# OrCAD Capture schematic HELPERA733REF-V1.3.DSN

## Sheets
1 00 Change log: title: HELPERA733_REF; rev: V1.3; company: szBaijie; note: Revision History
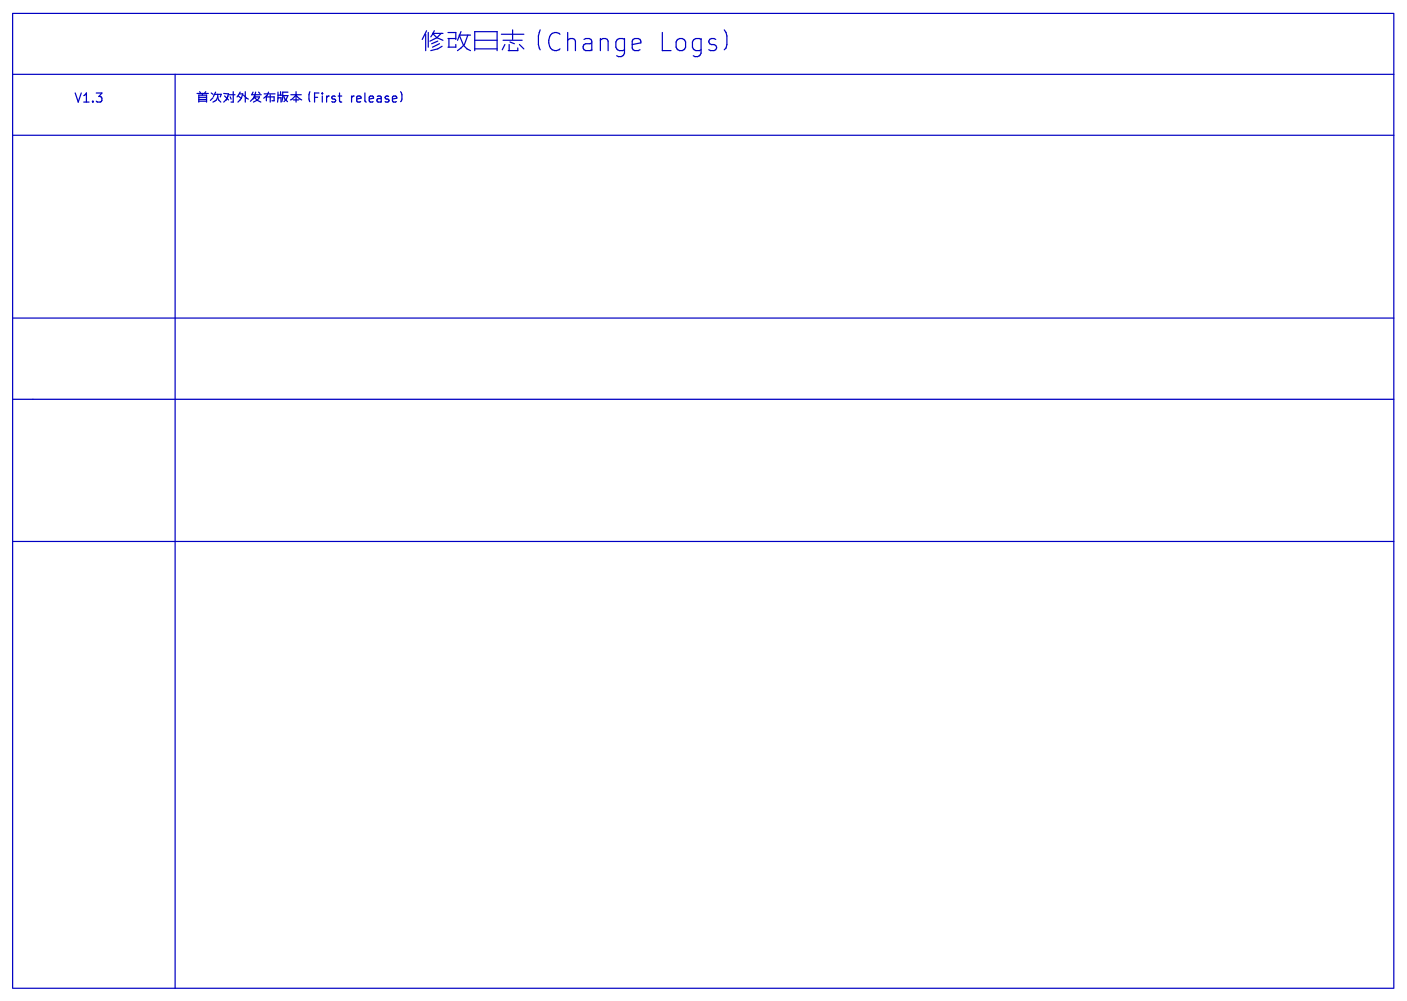
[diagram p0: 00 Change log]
2 01 CORE: size C; note: Core
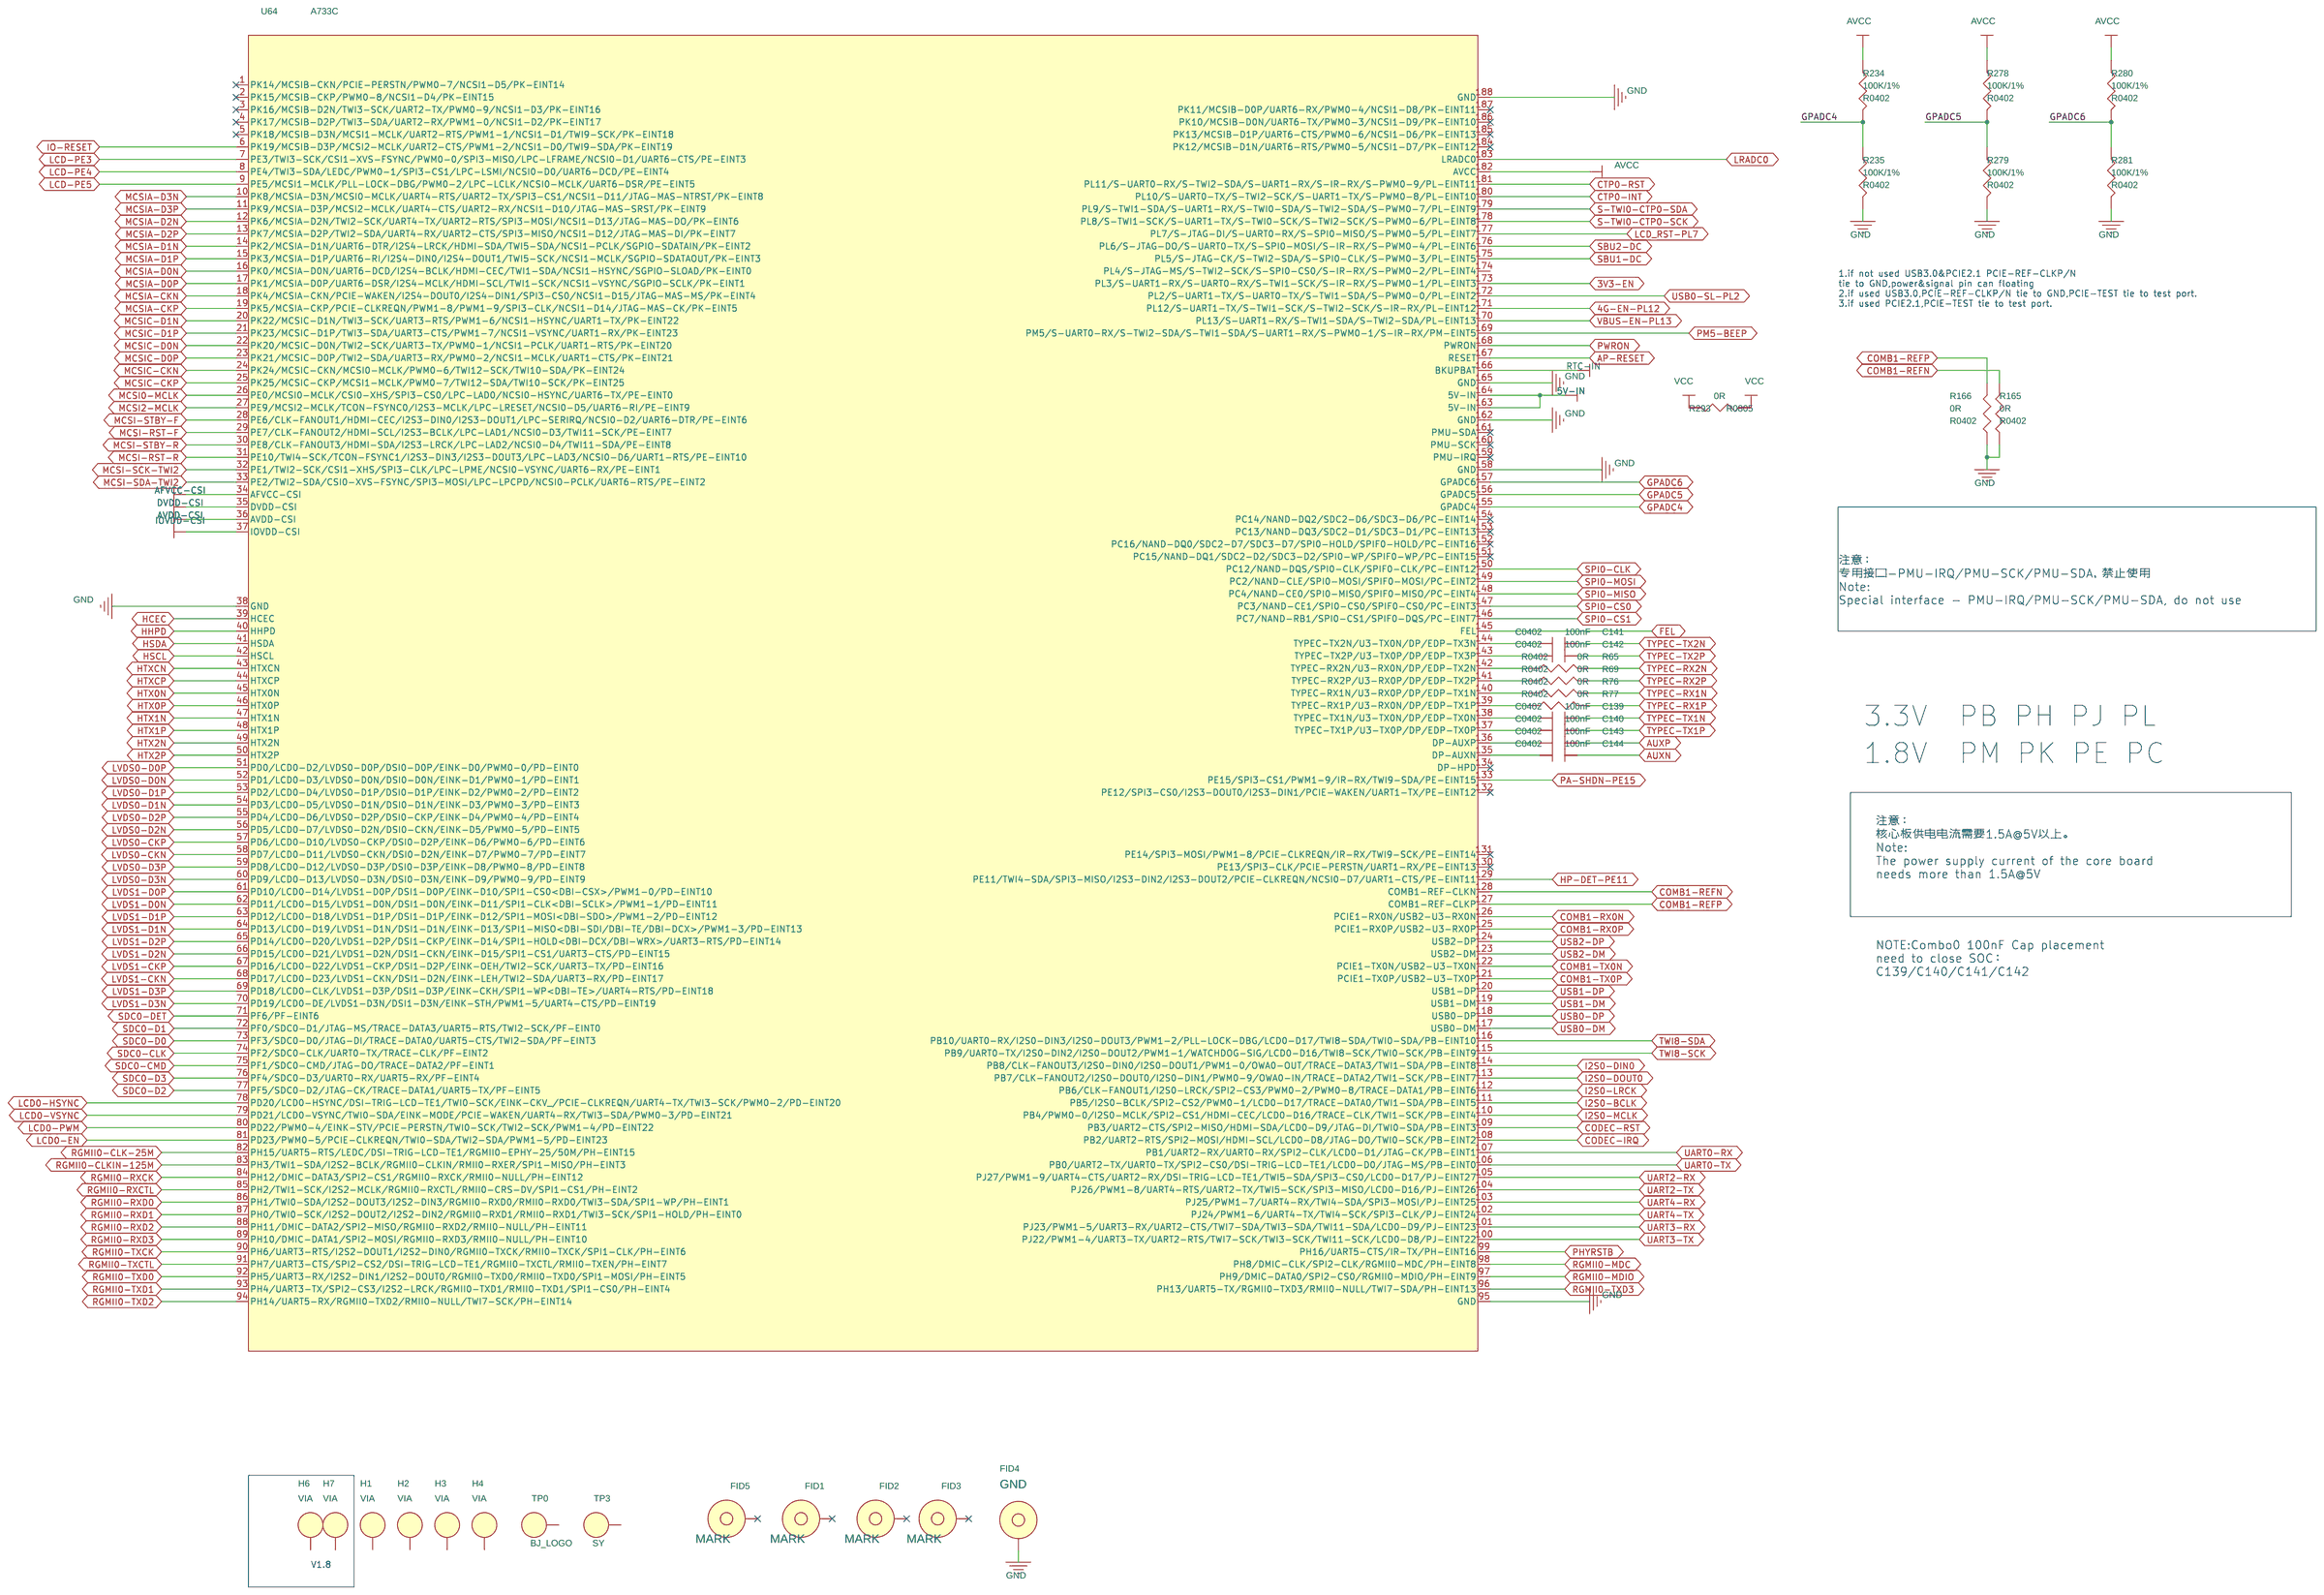
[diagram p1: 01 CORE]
3 02 Power: size B; note: Power
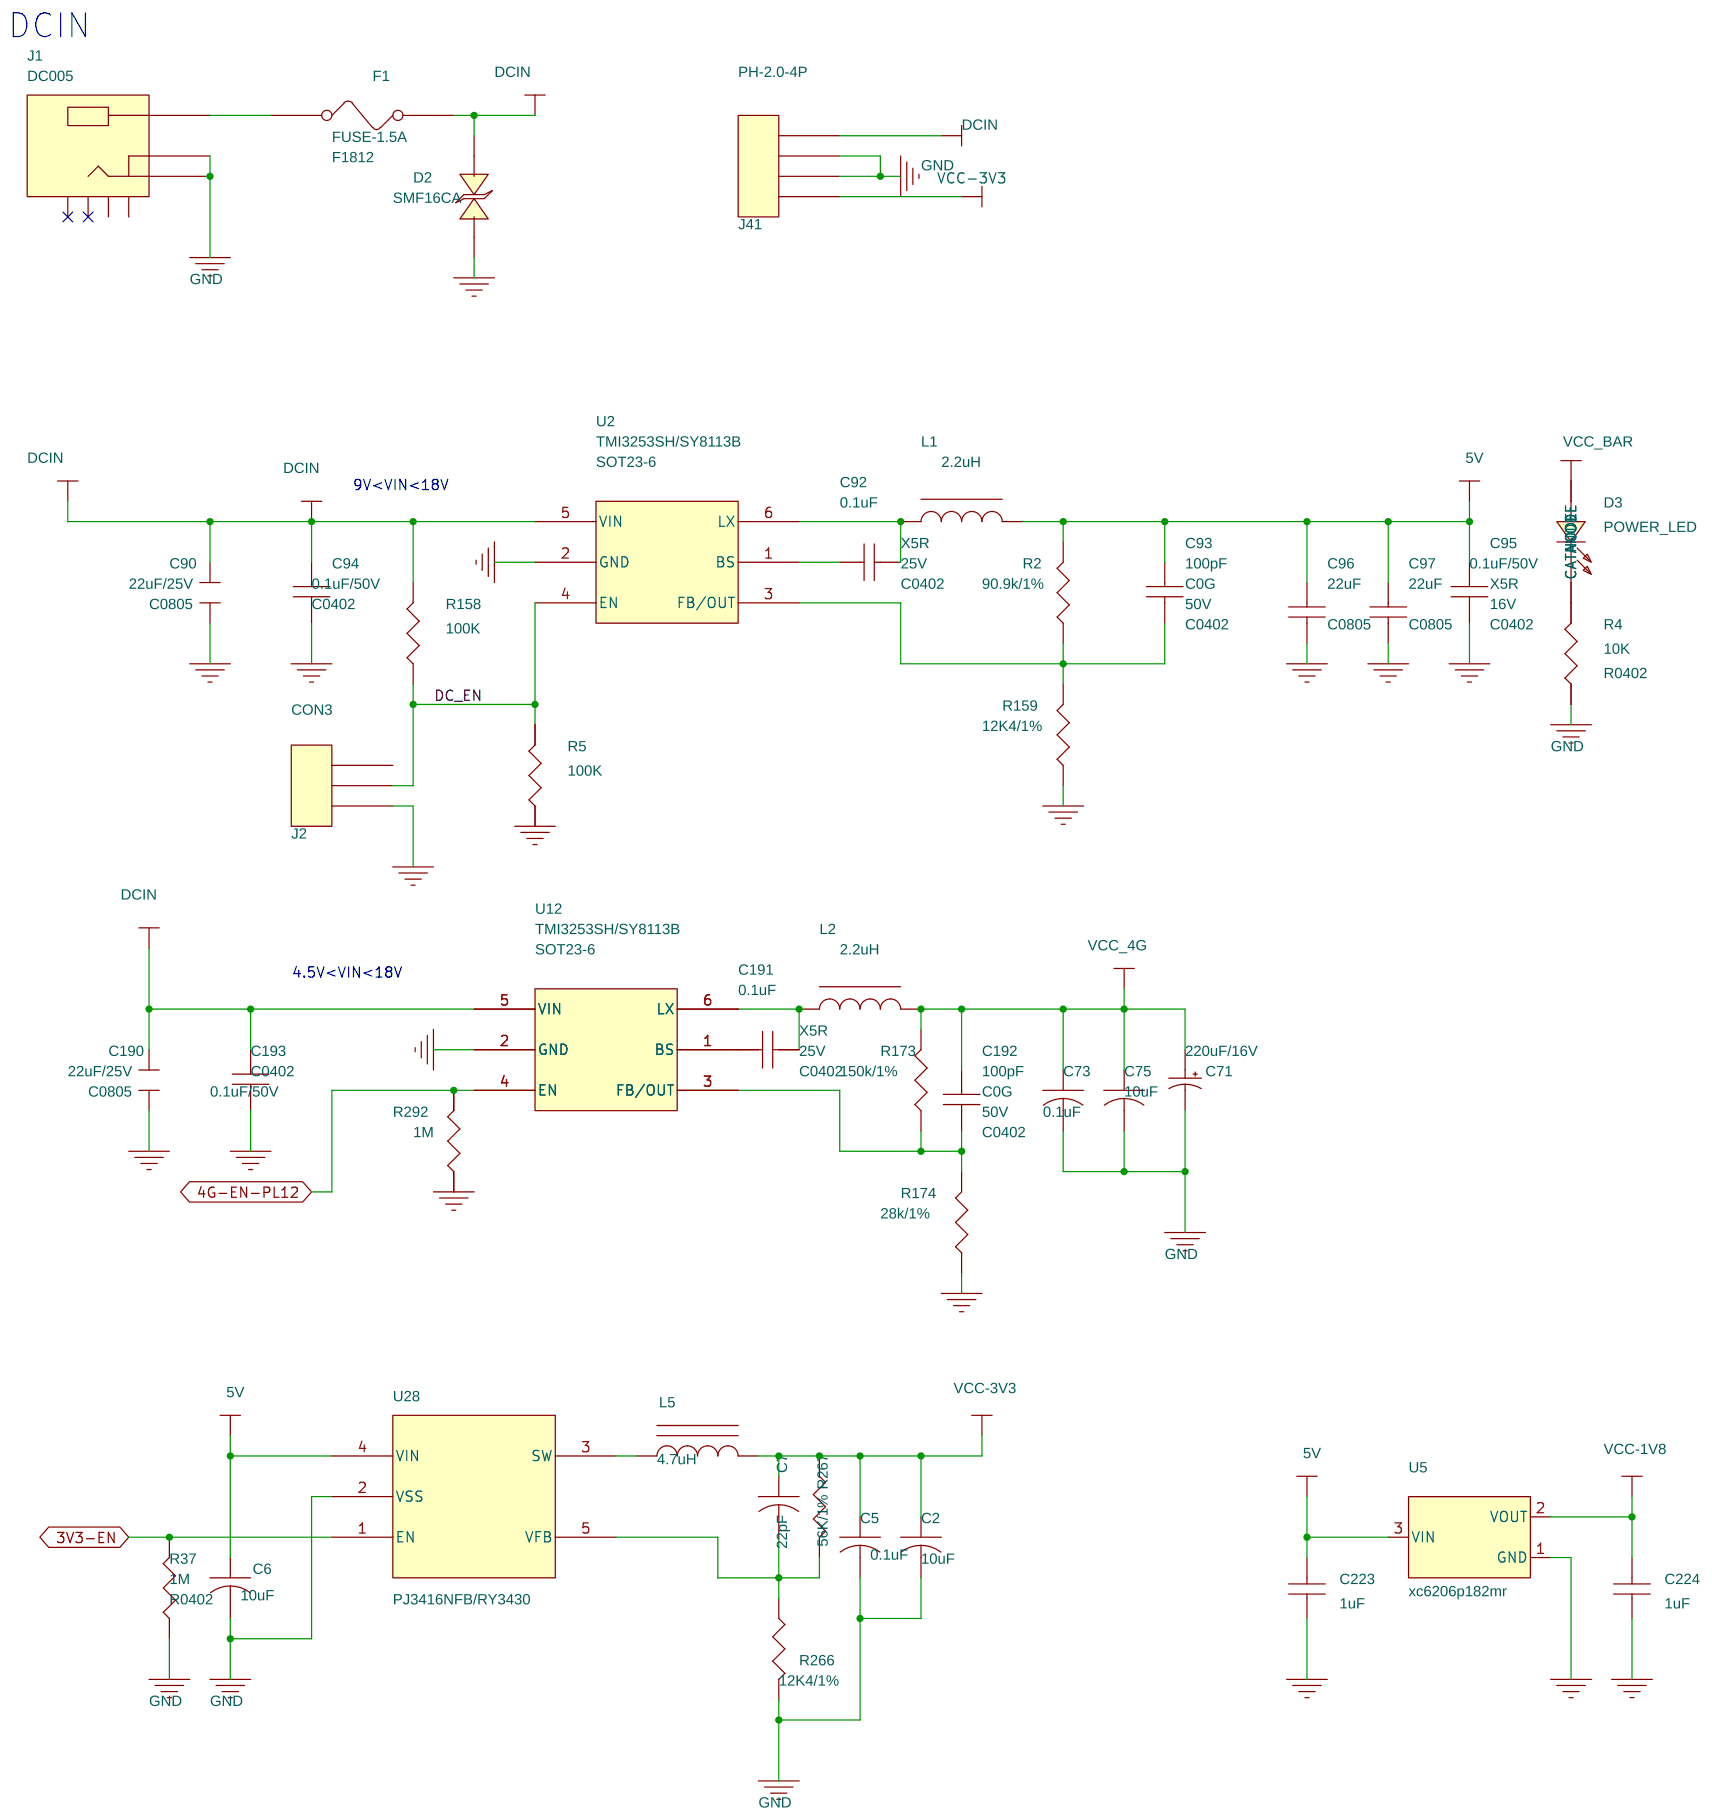
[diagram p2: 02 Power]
4 03 CAMERA: size Custom; note: Camera
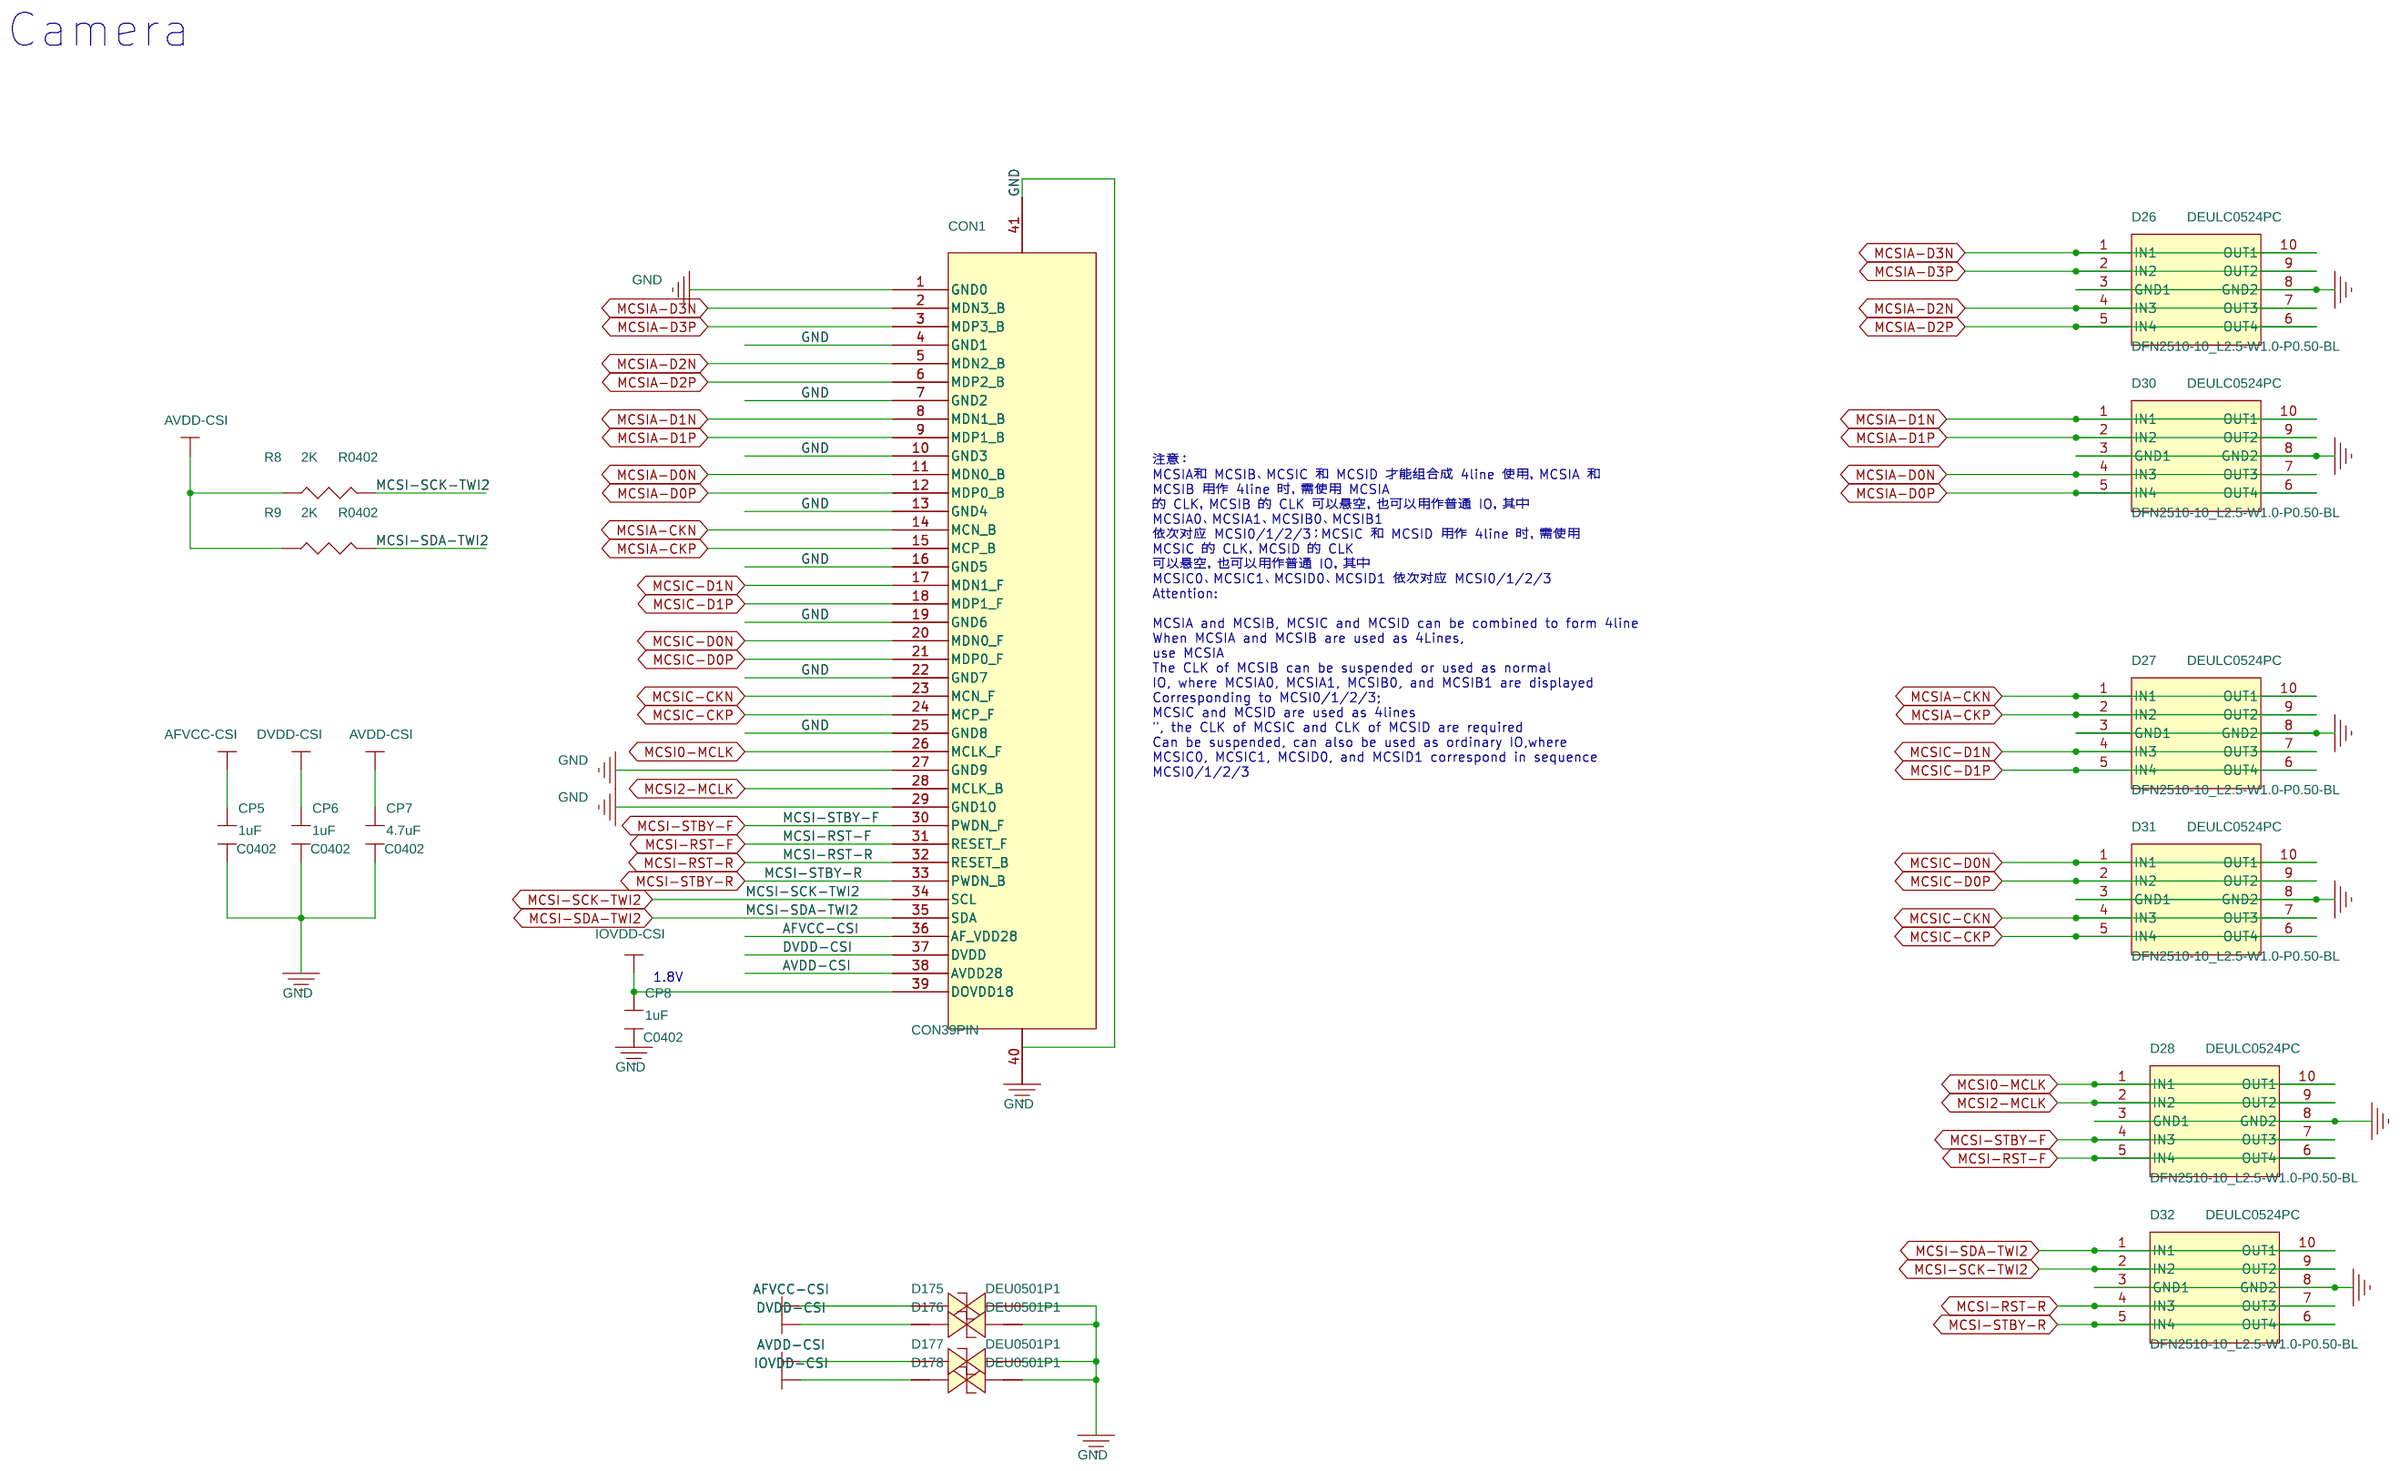
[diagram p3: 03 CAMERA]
5 04 LCD: size C; note: LCD
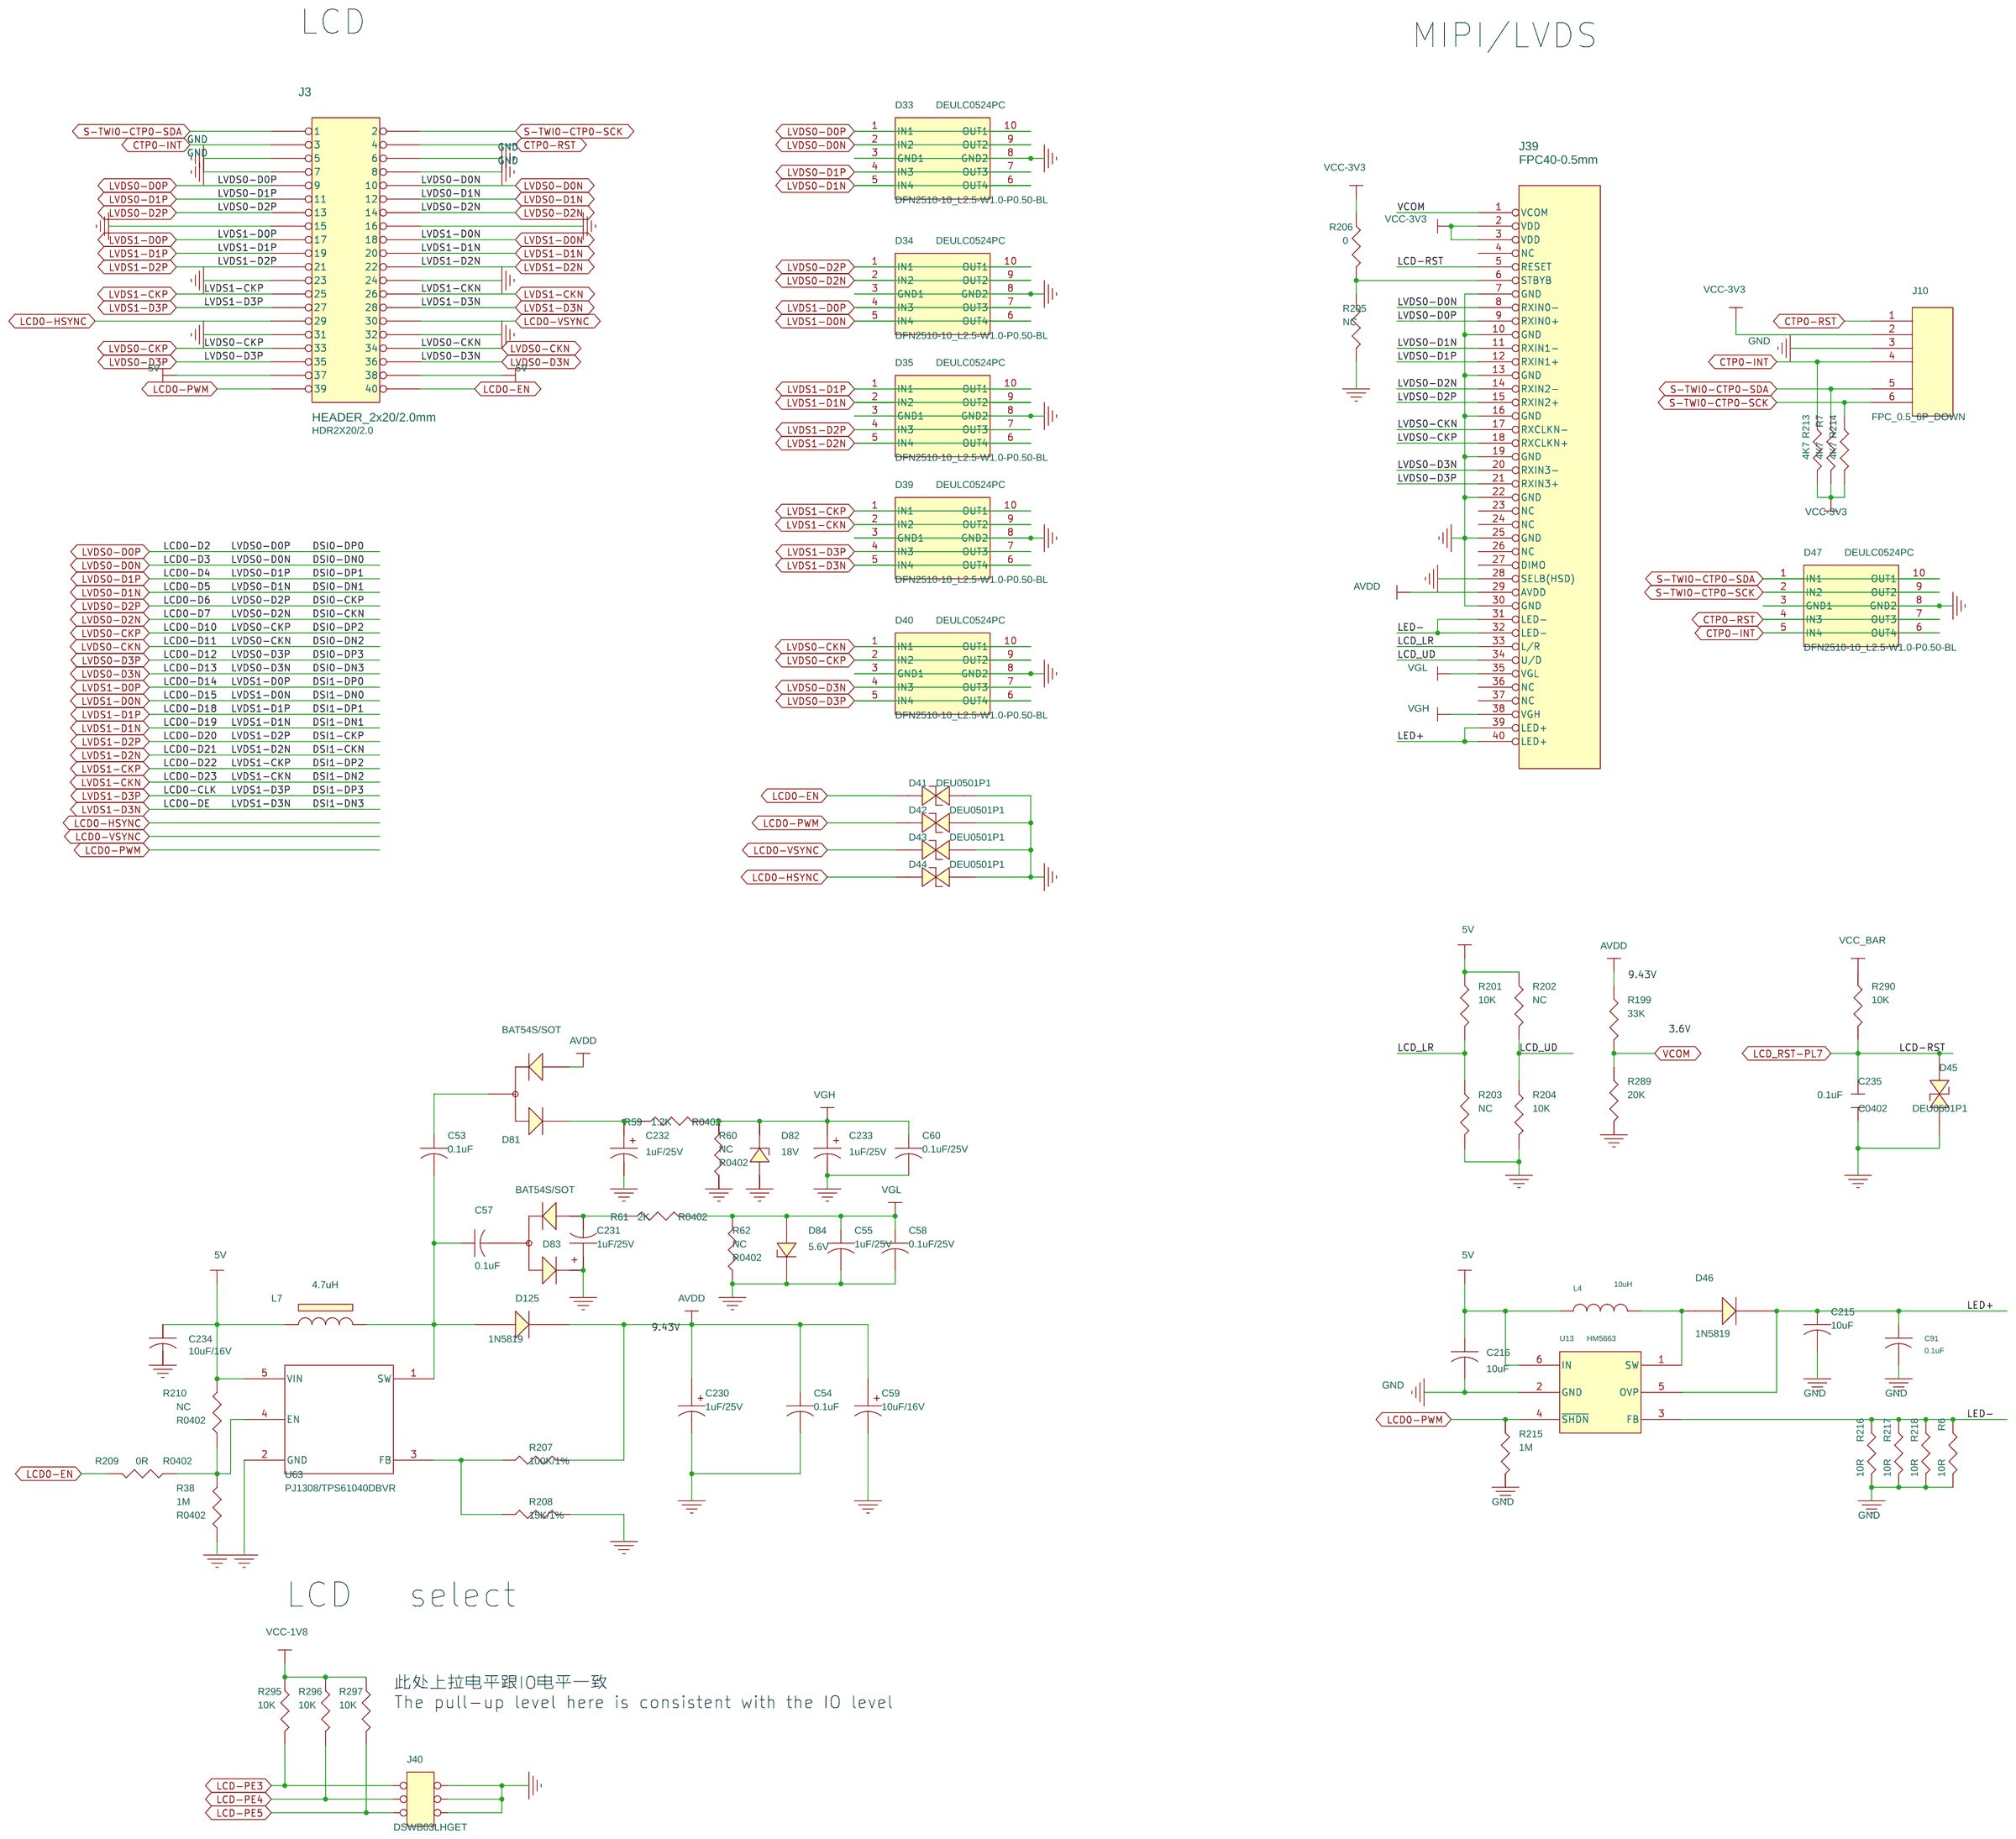
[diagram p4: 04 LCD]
6 07 4G: size A; note: 4G
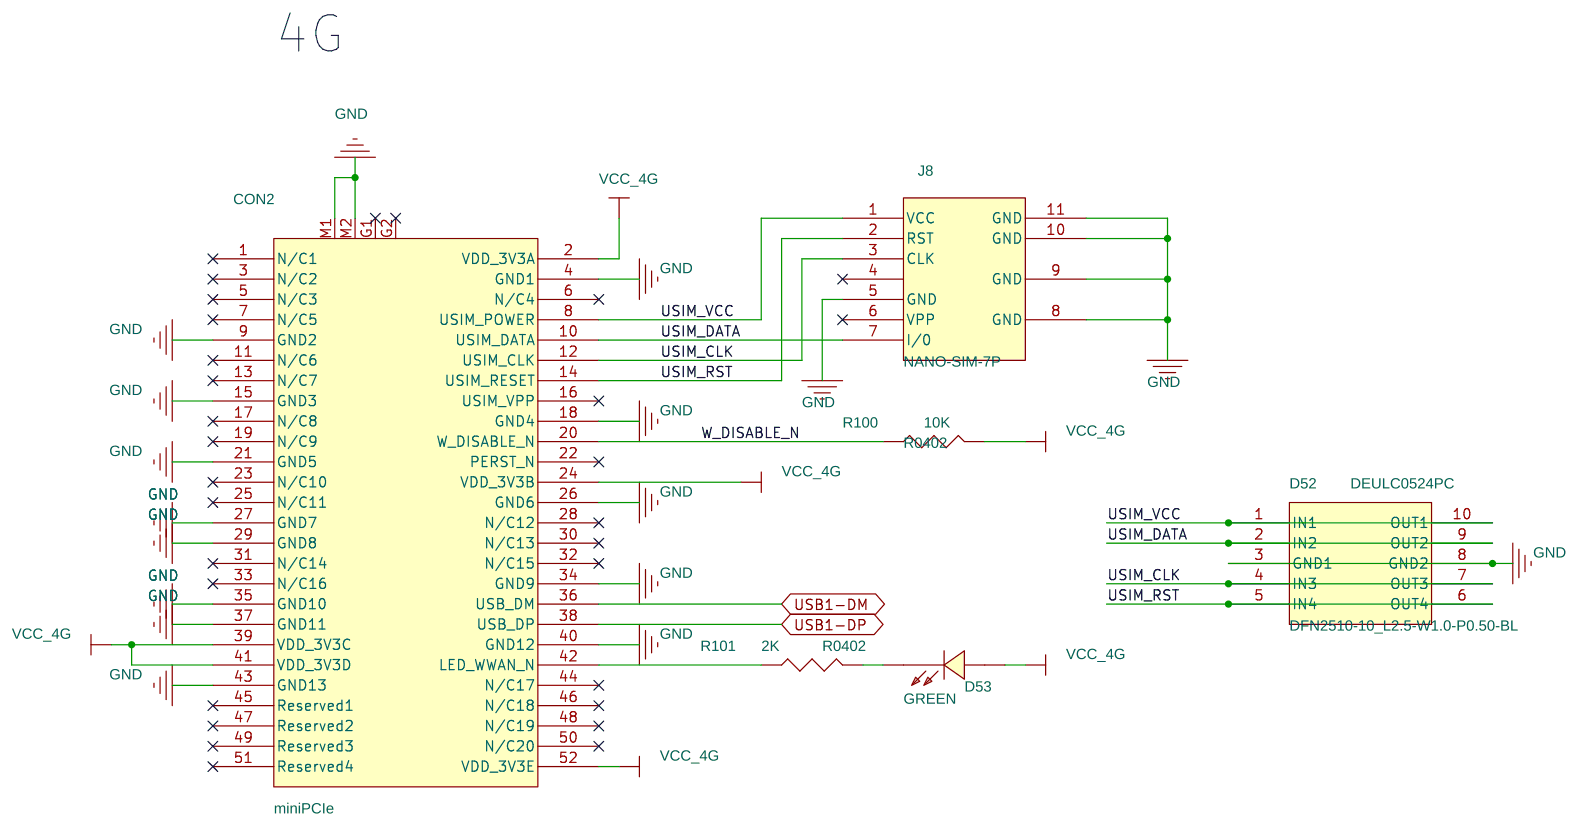
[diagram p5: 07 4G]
7 10 Ethernet: size B; note: Ethernet
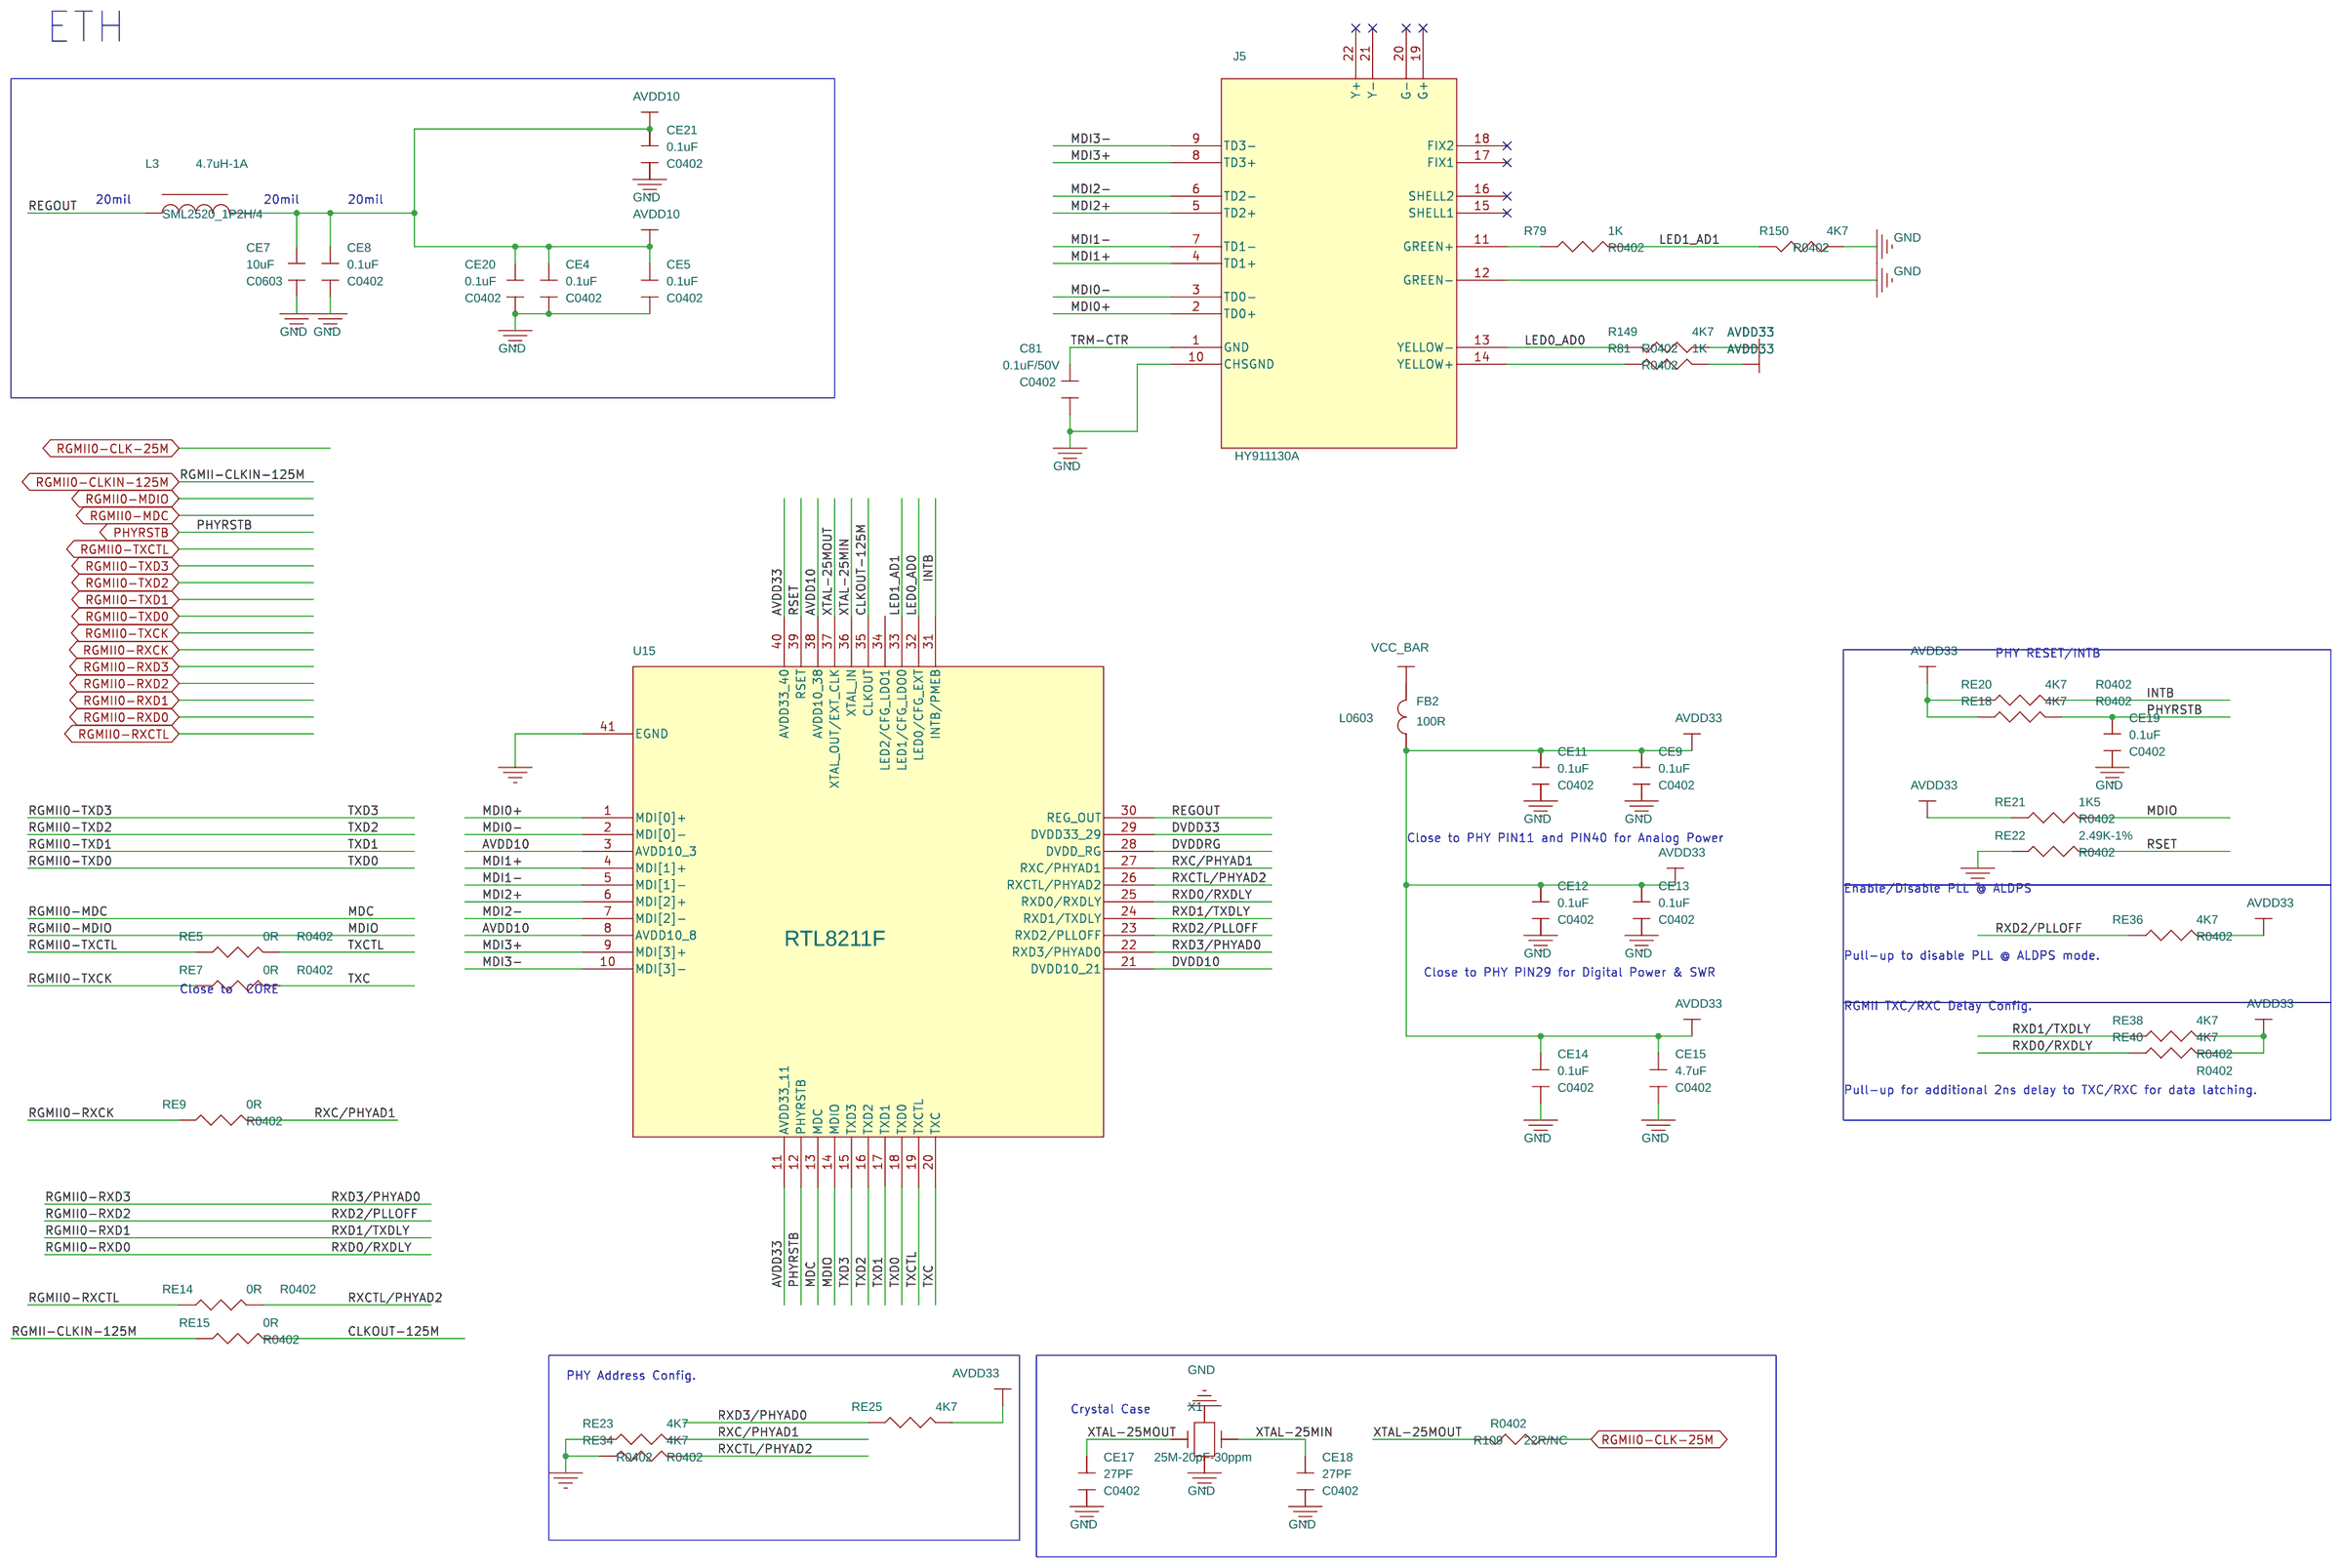
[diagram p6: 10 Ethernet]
8 12 HDMI: size A; note: HDMI
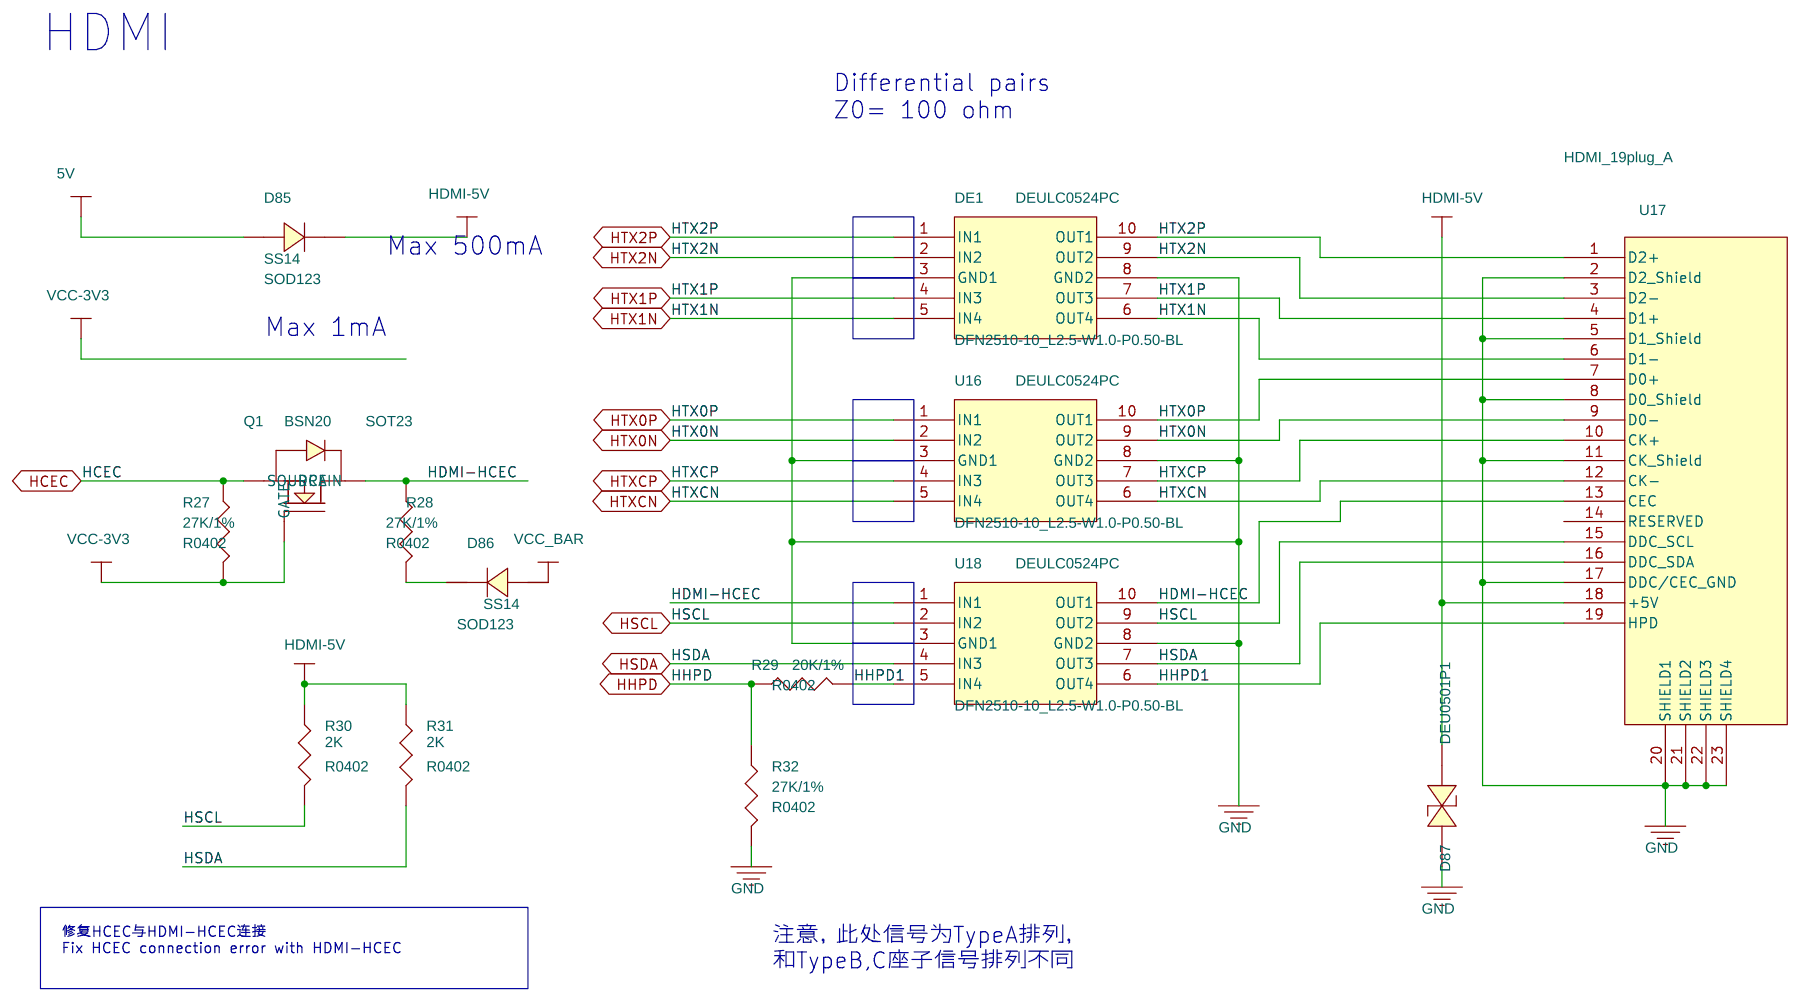
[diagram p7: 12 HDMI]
9 08  UART/485: size A; note: UART/485/CAN
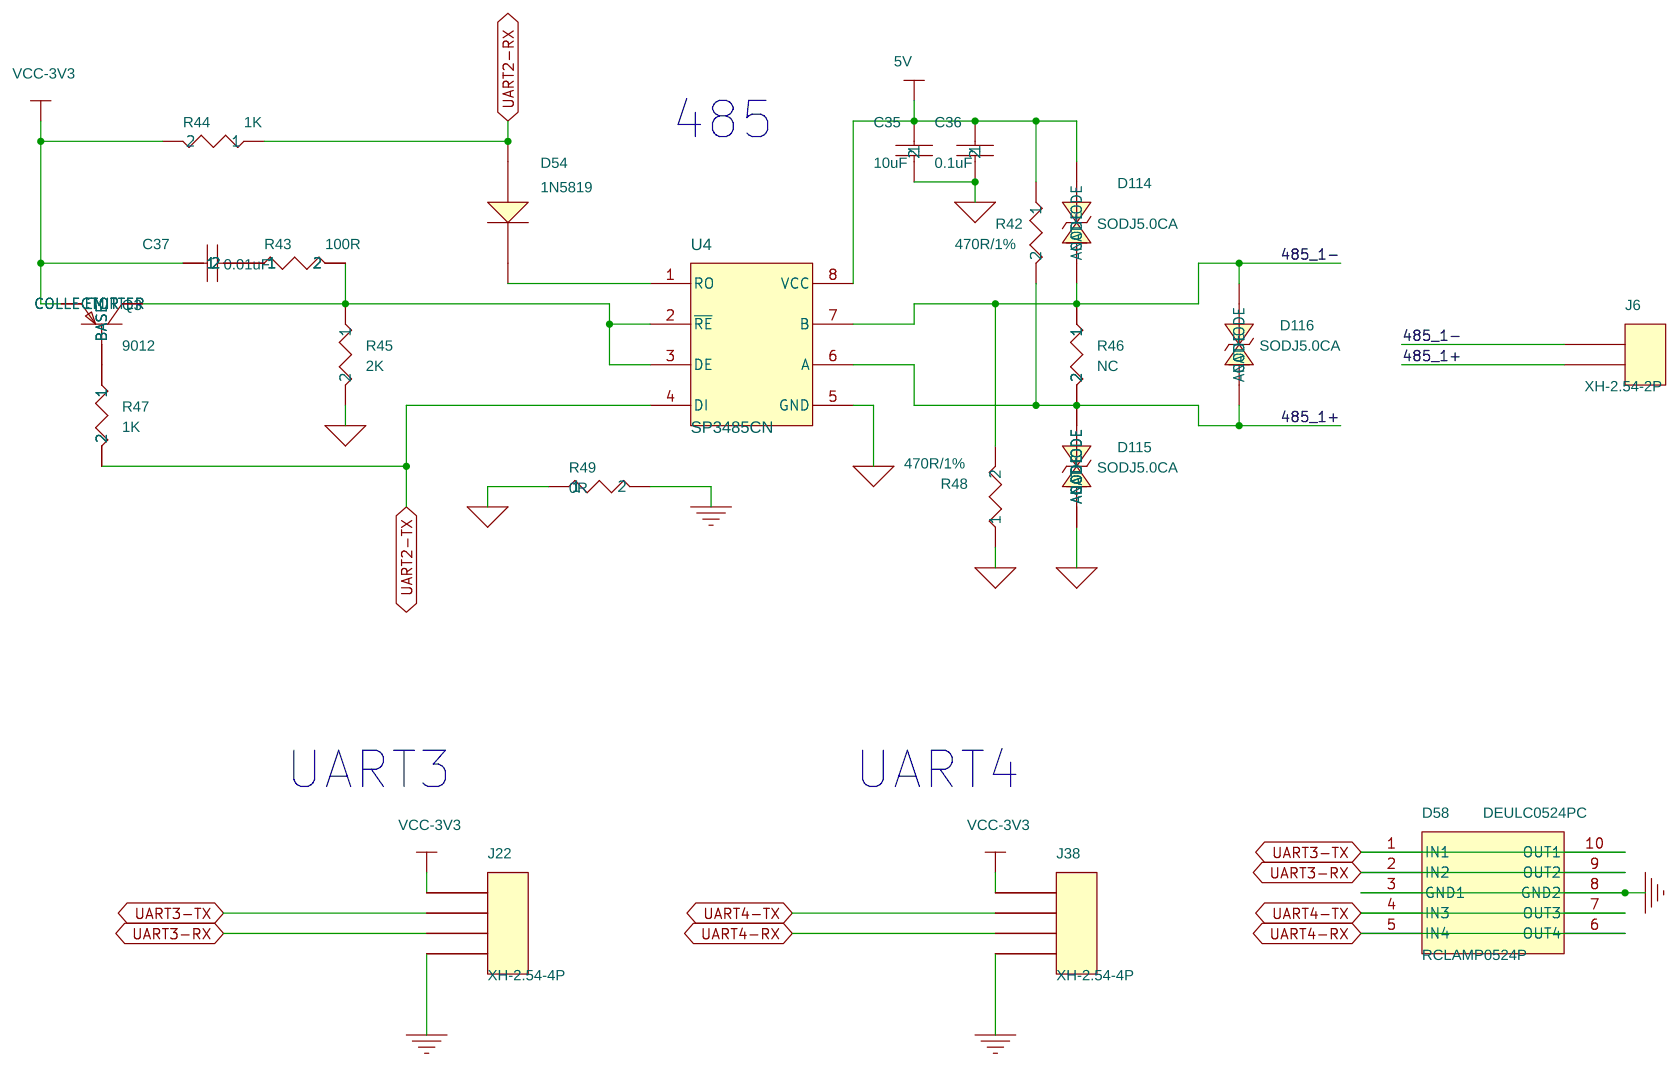
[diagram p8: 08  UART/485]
10 05 TF/KEY/RTC: size B; note: TF/KEY/RTC
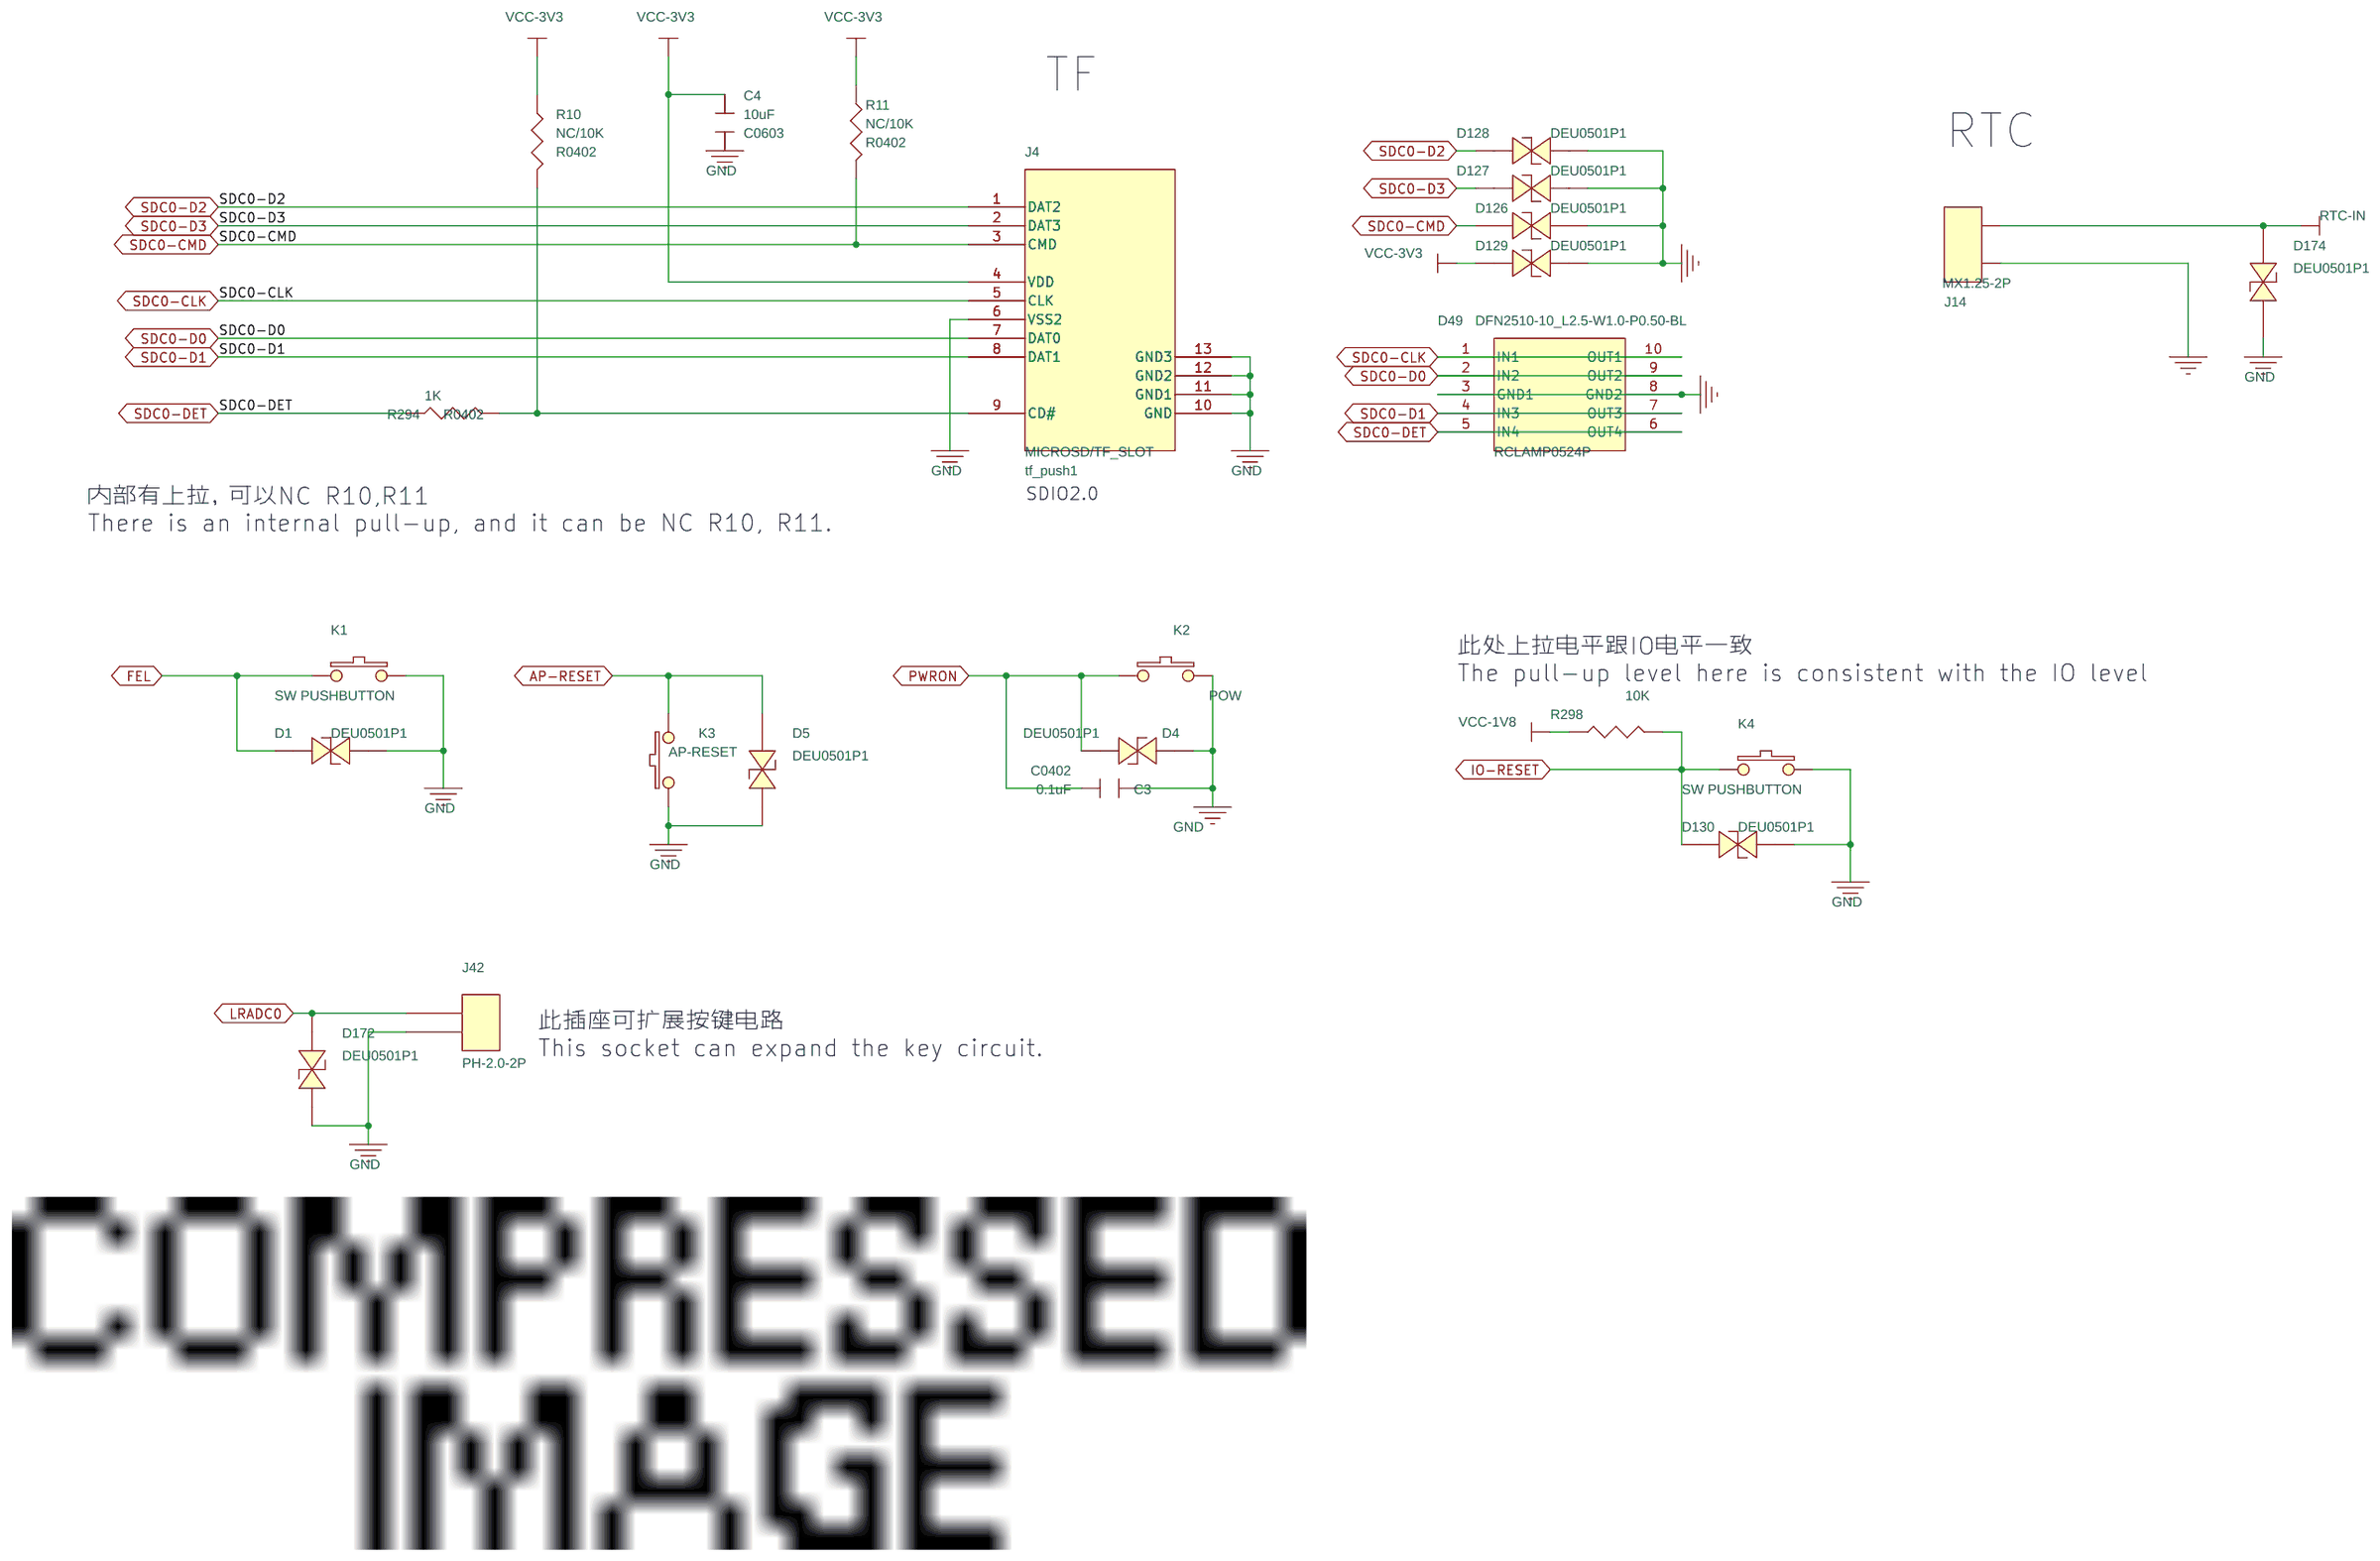
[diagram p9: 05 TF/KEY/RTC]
11 11 USB3.0/host: size C; note: USB3.0/host
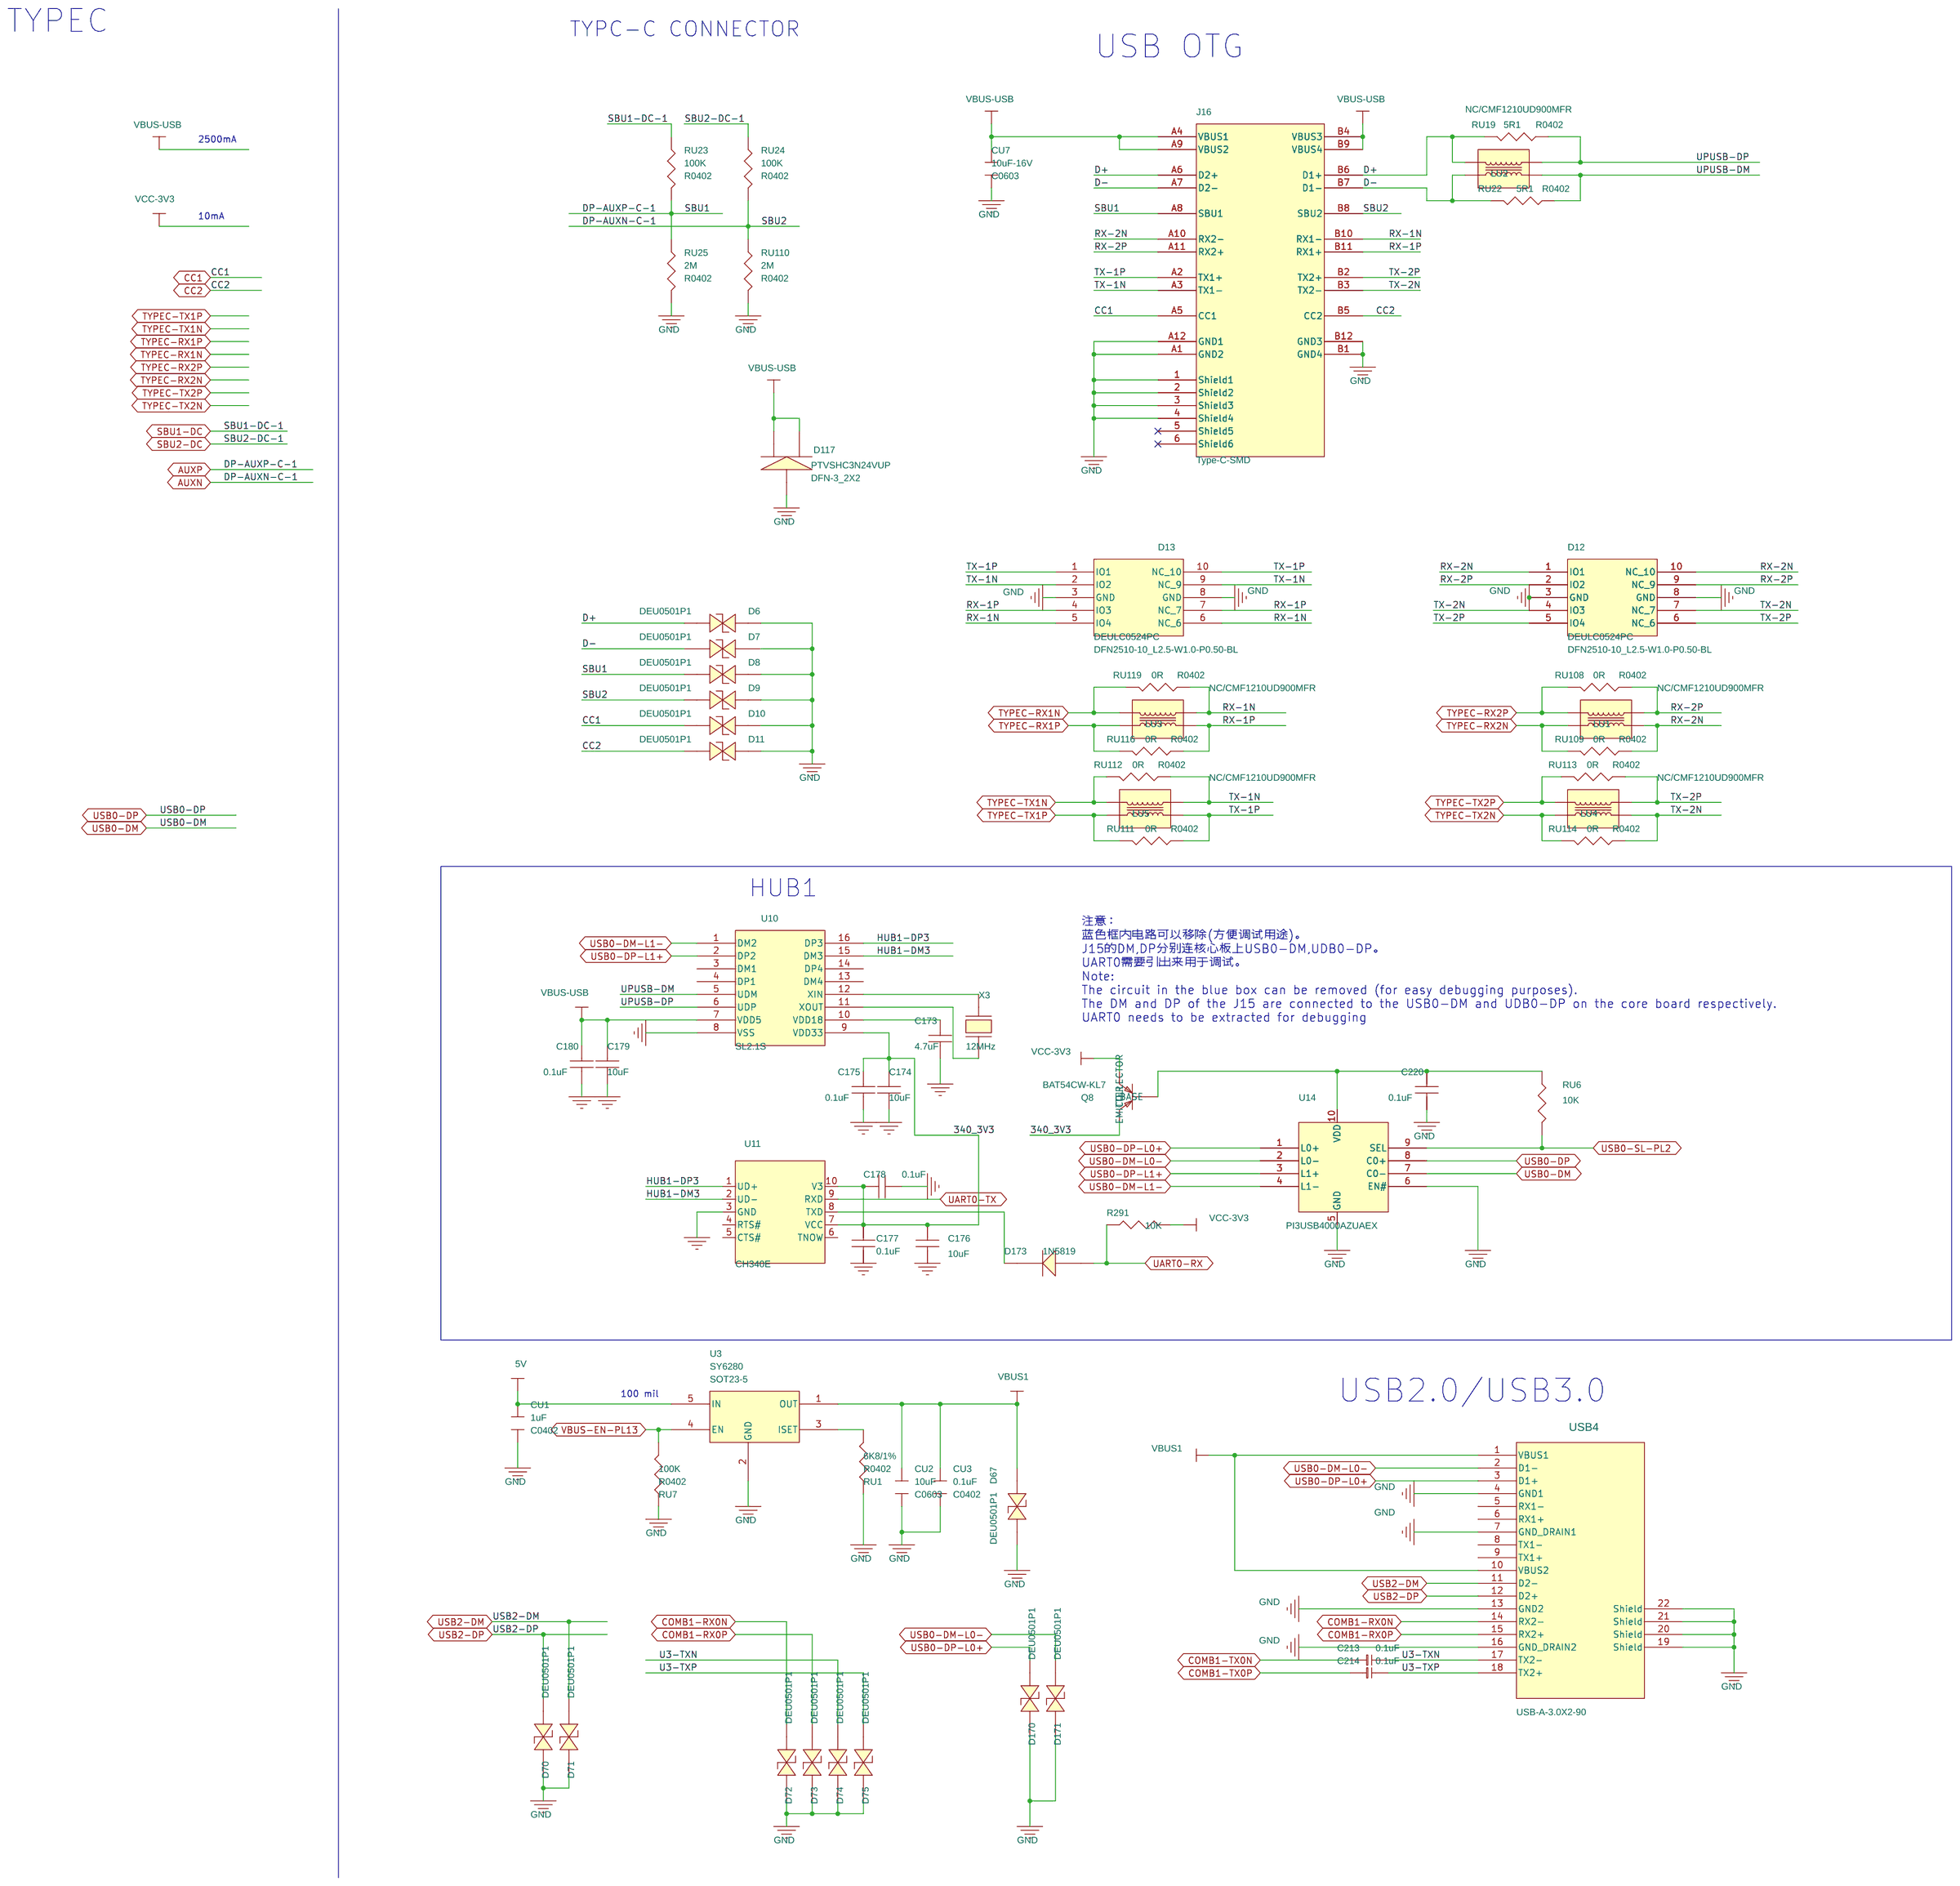
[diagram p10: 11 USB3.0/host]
12 09 IO/ADC/BEEP: size A; note: IO/ADC/BEEP
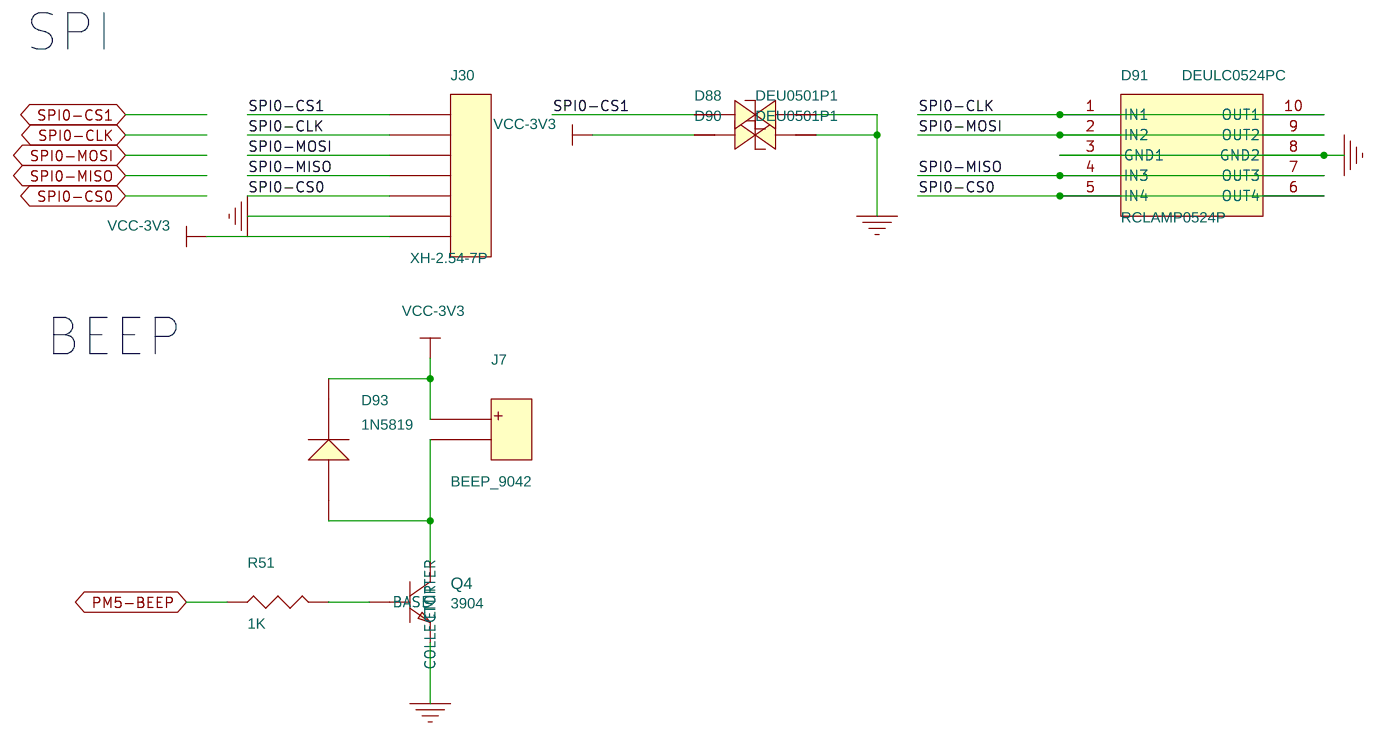
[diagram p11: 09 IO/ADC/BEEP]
13 06 AUDIO AC101/AC101B: size C; note: IO/ADC/BEEP
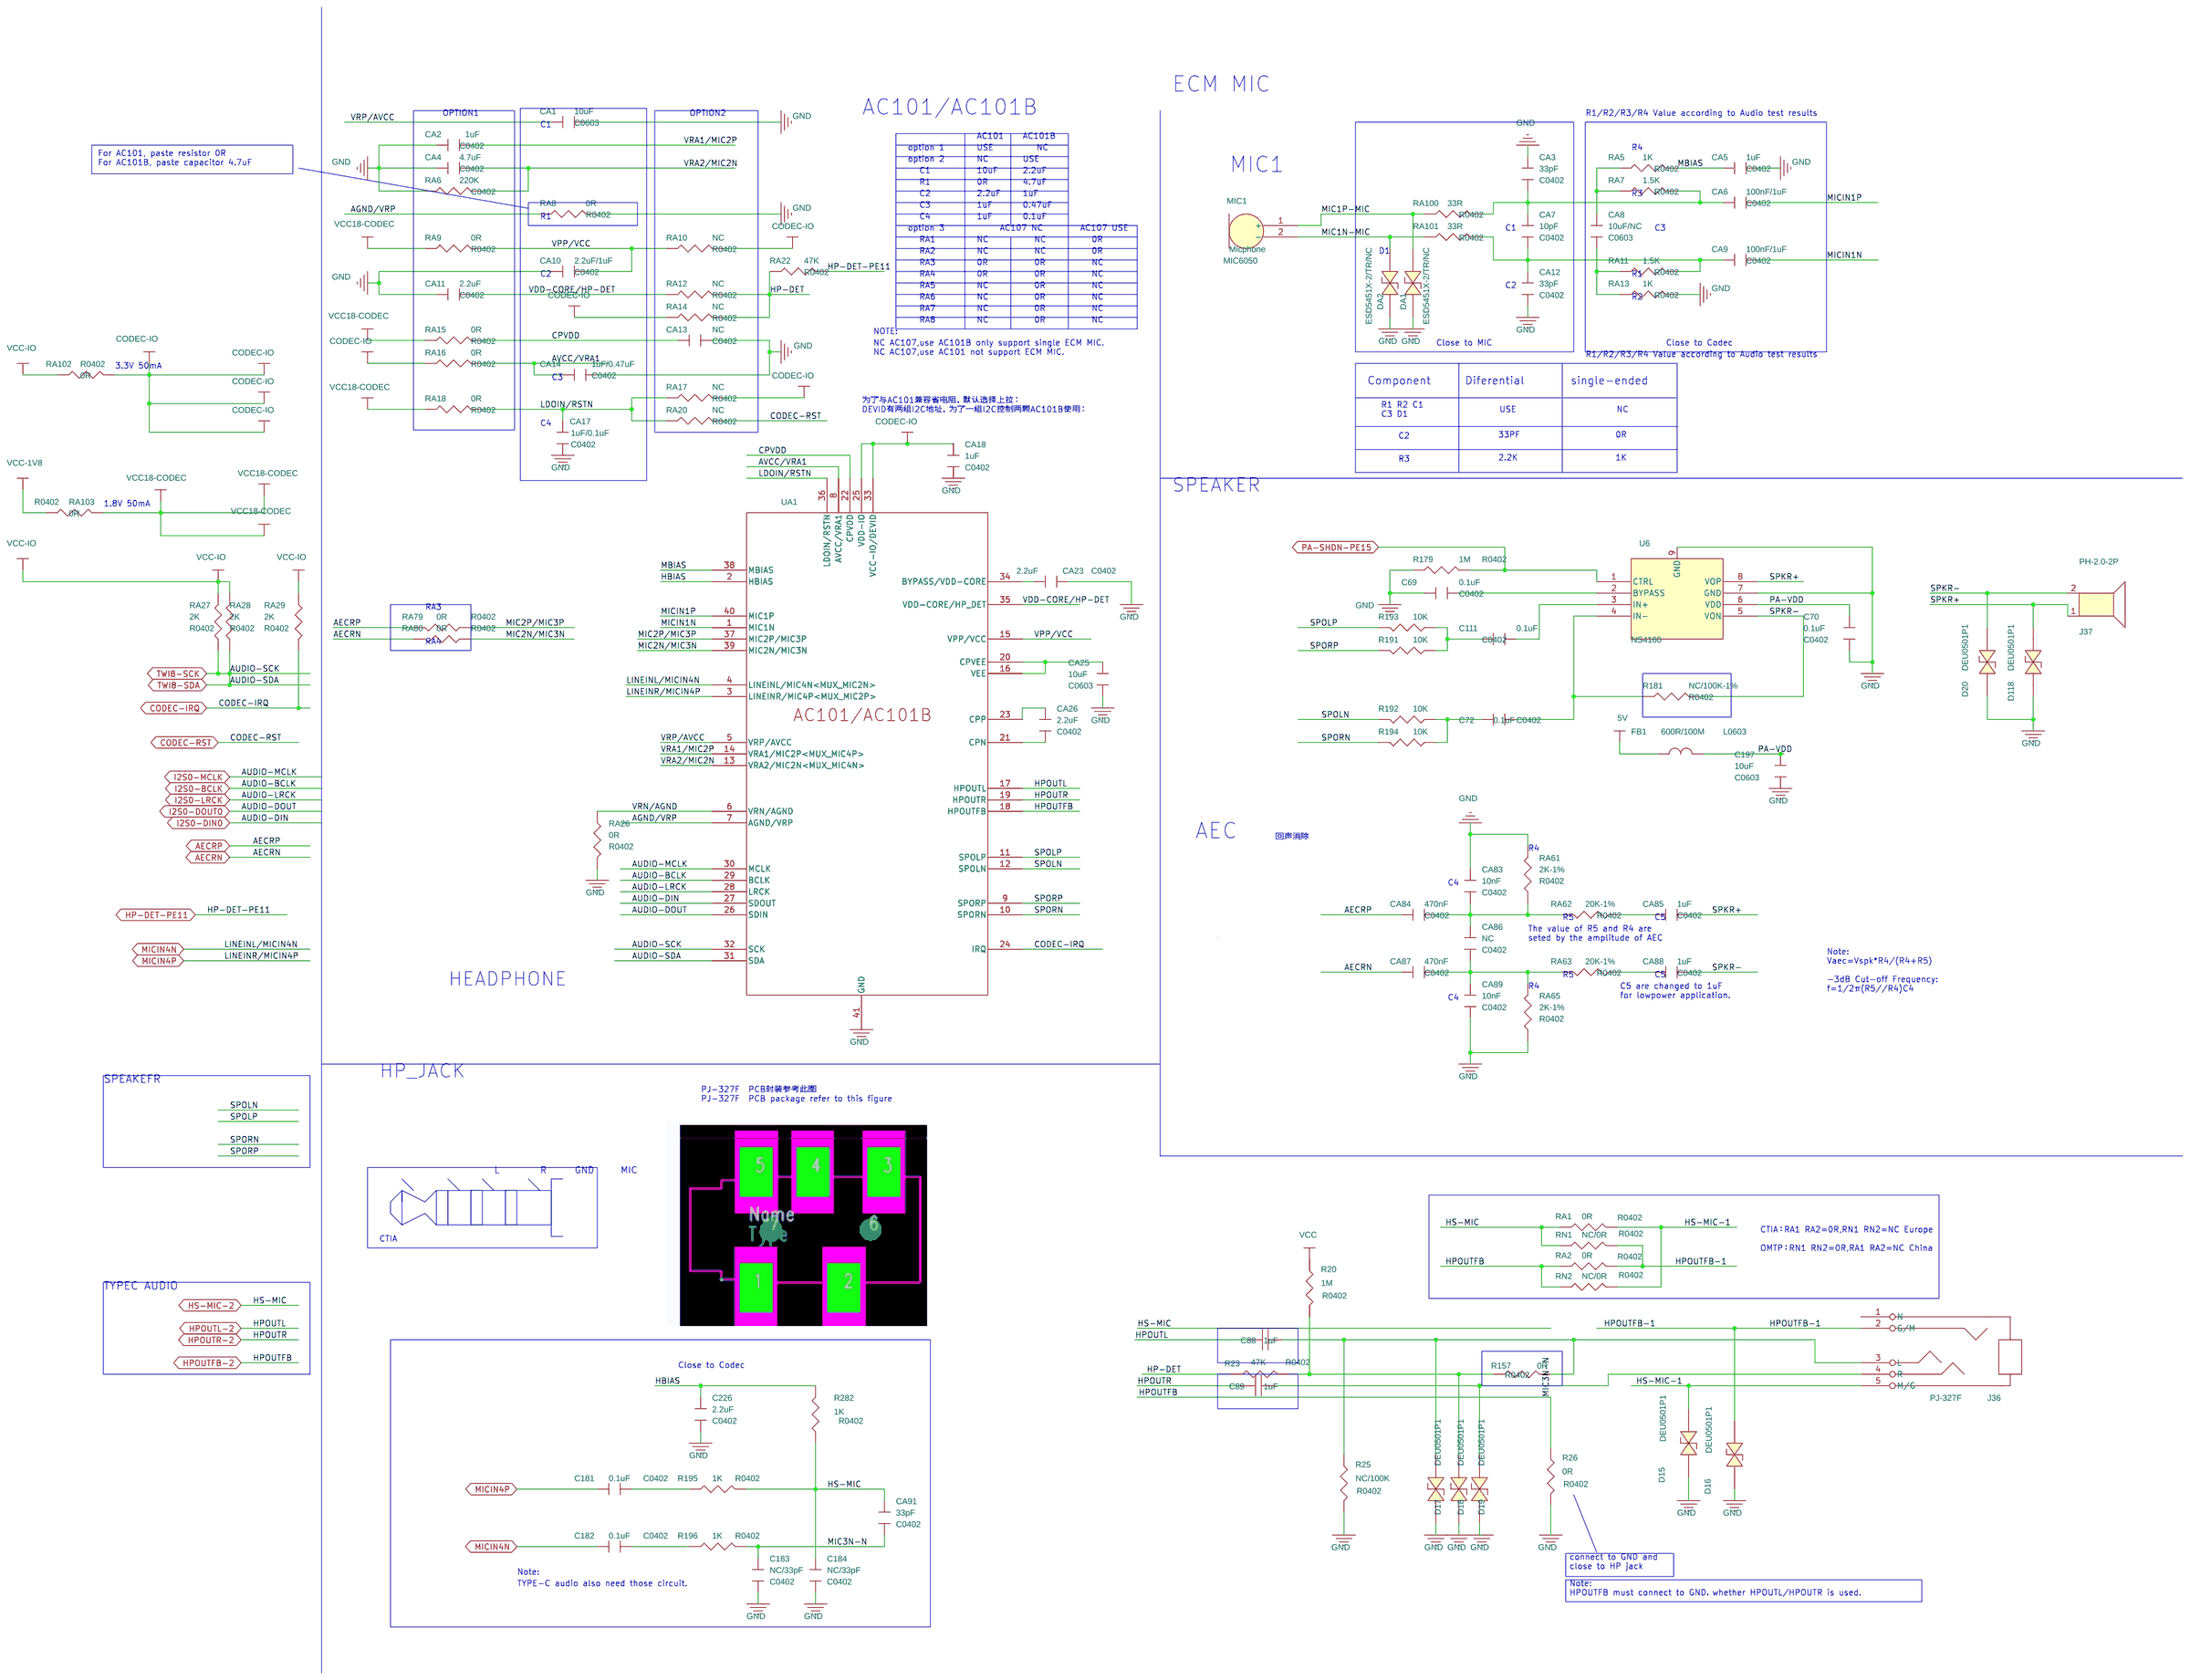
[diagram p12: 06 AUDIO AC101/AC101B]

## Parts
sheet 01 CORE
C139  100nF  [C0402]
C140  100nF  [C0402]
C141  100nF  [C0402]
C142  100nF  [C0402]
C143  100nF  [C0402]
C144  100nF  [C0402]
FID1  MARK  [MARK]
FID2  MARK  [MARK]
FID3  MARK  [MARK]
FID4  GND  [DV]
FID5  MARK  [MARK]
H1  VIA  [DV]
H2  VIA  [DV]
H3  VIA  [DV]
H4  VIA  [DV]
H6  VIA  [DV]
H7  VIA  [DV]
R65  0R  [R0402]
R69  0R  [R0402]
R76  0R  [R0402]
R77  0R  [R0402]
R165  0R  [R0402]
R166  0R  [R0402]
R234  100K/1%  [R0402]
R235  100K/1%  [R0402]
R278  100K/1%  [R0402]
R279  100K/1%  [R0402]
R280  100K/1%  [R0402]
R281  100K/1%  [R0402]
R293  0R  [R0805]
TP0  BJ_LOGO  [BJ_LOGO]
TP3  SY  [6X6]
U64  A733C  [HELPERA733D-1]
sheet 02 Power
C2  10uF  [C0603]
C5  0.1uF  [C0402]
C6  10uF  [C0603]
C7  22pF  [C0402]
C71  220uF/16V  [RB.1/.3]
C73  0.1uF  [C0402]
C75  10uF  [C0603]
C90  22uF/25V  [C0805]
C92  0.1uF  [C0402]
C93  100pF  [C0402]
C94  0.1uF/50V  [C0402]
C95  0.1uF/50V  [C0402]
C96  22uF  [C0805]
C97  22uF  [C0805]
C190  22uF/25V  [C0805]
C191  0.1uF  [C0402]
C192  100pF  [C0402]
C193  0.1uF/50V  [C0402]
C223  1uF  [C0402]
C224  1uF  [C0402]
D2  SMF16CA  [SOD123]
D3  POWER_LED  [D0603]
F1  FUSE-1.5A  [F1812]
J1  DC005  [DC470]
J2  CON3  [SS-12F44(1P2T)]
J41  PH-2.0-4P  [PH-2.0-4P]
L1  2.2uH  [4018]
L2  2.2uH  [4018]
L5  4.7uH  [4018]
R2  90.9k/1%  [R0402]
R4  10K  [R0402]
R5  100K  [R0402]
R37  1M  [R0402]
R158  100K  [R0402]
R159  12K4/1%  [R0402]
R173  150k/1%  [R0402]
R174  28k/1%  [R0402]
R266  12K4/1%  [R0402]
R267  56K/1%  [R0402]
R292  1M  [R0402]
U2  TMI3253SH/SY8113B  [SOT23-6]
U5  xc6206p182mr  [SOT23]
U12  TMI3253SH/SY8113B  [SOT23-6]
U28  PJ3416NFB/RY3430  [SOT23-5]
sheet 03 CAMERA
CON1  CON39PIN  [FH35C-39S-0.3SHW]
CP5  1uF  [C0402]
CP6  1uF  [C0402]
CP7  4.7uF  [C0402]
CP8  1uF  [C0402]
D26  DEULC0524PC  [DFN2510-10_L2.5-W1.0-P0.50-BL]
D27  DEULC0524PC  [DFN2510-10_L2.5-W1.0-P0.50-BL]
D28  DEULC0524PC  [DFN2510-10_L2.5-W1.0-P0.50-BL]
D30  DEULC0524PC  [DFN2510-10_L2.5-W1.0-P0.50-BL]
D31  DEULC0524PC  [DFN2510-10_L2.5-W1.0-P0.50-BL]
D32  DEULC0524PC  [DFN2510-10_L2.5-W1.0-P0.50-BL]
D175  DEU0501P1  [ESD0402]
D176  DEU0501P1  [ESD0402]
D177  DEU0501P1  [ESD0402]
D178  DEU0501P1  [ESD0402]
R8  2K  [R0402]
R9  2K  [R0402]
sheet 04 LCD
C53  0.1uF  [C0402]
C54  0.1uF  [C0402]
C55  1uF/25V  [C0805]
C57  0.1uF  [C0402]
C58  0.1uF/25V  [C0402]
C59  10uF/16V  [C0805]
C60  0.1uF/25V  [C0402]
C91  0.1uF  [C0402]
C215  10uF  [C0603]
C216  10uF  [C0603]
C230  1uF/25V  [C0805]
C231  1uF/25V  [C0805]
C232  1uF/25V  [C0805]
C233  1uF/25V  [C0805]
C234  10uF/16V  [C0805]
C235  0.1uF  [C0402]
D33  DEULC0524PC  [DFN2510-10_L2.5-W1.0-P0.50-BL]
D34  DEULC0524PC  [DFN2510-10_L2.5-W1.0-P0.50-BL]
D35  DEULC0524PC  [DFN2510-10_L2.5-W1.0-P0.50-BL]
D39  DEULC0524PC  [DFN2510-10_L2.5-W1.0-P0.50-BL]
D40  DEULC0524PC  [DFN2510-10_L2.5-W1.0-P0.50-BL]
D41  DEU0501P1  [ESD0402]
D42  DEU0501P1  [ESD0402]
D43  DEU0501P1  [ESD0402]
D44  DEU0501P1  [ESD0402]
D45  DEU0501P1  [ESD0402]
D46  1N5819  [SOD323]
D47  DEULC0524PC  [DFN2510-10_L2.5-W1.0-P0.50-BL]
D81  BAT54S/SOT  [SOT23]
D82  18V  [D0805]
D83  BAT54S/SOT  [SOT23]
D84  5.6V  [D0805]
D125  1N5819  [D0805]
J3  HEADER_2x20/2.0mm  [HDR2X20/2.0]
J10  FPC_0.5_6P_DOWN  [FPC_0.5_6P_DOWN]
J39  FPC40-0.5mm  [FPC40-0.5MM-UP]
J40  DSWB03LHGET  [SW-TH-DSWB03LHGET]
L4  10uH  [4018]
L7  4.7uH  [4018]
R6  10R  [R0402]
R7  4K7  [R0402]
R38  1M  [R0402]
R59  1.2K  [R0402]
R60  NC  [R0402]
R61  2K  [R0402]
R62  NC  [R0402]
R199  33K  [R0402]
R201  10K  [R0402]
R202  NC  [R0402]
R203  NC  [R0402]
R204  10K  [R0402]
R205  NC  [R0402]
R206  0  [R0402]
R207  100K/1%  [R0402]
R208  15K/1%  [R0402]
R209  0R  [R0402]
R210  NC  [R0402]
R213  4K7  [R0402]
R214  4K7  [R0402]
R215  1M  [R0402]
R216  10R  [R0402]
R217  10R  [R0402]
R218  10R  [R0402]
R289  20K  [R0402]
R290  10K  [R0402]
R295  10K  [R0402]
R296  10K  [R0402]
R297  10K  [R0402]
U13  HM5663  [SOT23-6]
U63  PJ1308/TPS61040DBVR  [SOT23-5]
sheet 05 TF/KEY/RTC
C3  0.1uF  [C0402]
C4  10uF  [C0603]
D1  DEU0501P1  [ESD0402]
D4  DEU0501P1  [ESD0402]
D5  DEU0501P1  [ESD0402]
D49  DFN2510-10_L2.5-W1.0-P0.50-BL  [RCLAMP0524P]
D126  DEU0501P1  [ESD0402]
D127  DEU0501P1  [ESD0402]
D128  DEU0501P1  [ESD0402]
D129  DEU0501P1  [ESD0402]
D130  DEU0501P1  [ESD0402]
D172  DEU0501P1  [ESD0402]
D174  DEU0501P1  [ESD0402]
J4  MICROSD/TF_SLOT  [tf_push1]
J14  MX1.25-2P  [MX1.25-2P]
J42  PH-2.0-2P  [PH-2.0-2P]
K1  SW PUSHBUTTON  [KEY_3X4]
K2  POW  [KEY_3X4]
K3  AP-RESET  [KEY_3X4]
K4  SW PUSHBUTTON  [KEY_3X4]
R10  NC/10K  [R0402]
R11  NC/10K  [R0402]
R294  1K  [R0402]
R298  10K  [R0402]
sheet 06 AUDIO AC101/AC101B
C69  0.1uF  [C0402]
C70  0.1uF  [C0402]
C72  0.1uF  [C0402]
C88  1uF  [C0402]
C89  1uF  [C0402]
C111  0.1uF  [C0402]
C181  0.1uF  [C0402]
C182  0.1uF  [C0402]
C183  NC/33pF  [C0402]
C184  NC/33pF  [C0402]
C197  10uF  [C0603]
C226  2.2uF  [C0402]
CA1  10uF  [C0603]
CA2  1uF  [C0402]
CA3  33pF  [C0402]
CA4  4.7uF  [C0402]
CA5  1uF  [C0402]
CA6  100nF/1uF  [C0402]
CA7  10pF  [C0402]
CA8  10uF/NC  [C0603]
CA9  100nF/1uF  [C0402]
CA10  2.2uF/1uF  [C0402]
CA11  2.2uF  [C0402]
CA12  33pF  [C0402]
CA13  NC  [C0402]
CA14  1uF/0.47uF  [C0402]
CA17  1uF/0.1uF  [C0402]
CA18  1uF  [C0402]
CA23  2.2uF  [C0402]
CA25  10uF  [C0603]
CA26  2.2uF  [C0402]
CA83  10nF  [C0402]
CA84  470nF  [C0402]
CA85  1uF  [C0402]
CA86  NC  [C0402]
CA87  470nF  [C0402]
CA88  1uF  [C0402]
CA89  10nF  [C0402]
CA91  33pF  [C0402]
D15  DEU0501P1  [ESD0402]
D16  DEU0501P1  [ESD0402]
D17  DEU0501P1  [ESD0402]
D18  DEU0501P1  [ESD0402]
D19  DEU0501P1  [ESD0402]
D20  DEU0501P1  [ESD0402]
D118  DEU0501P1  [ESD0402]
DA1  ESD5451X-2/TR/NC  [ESD0402]
DA2  ESD5451X-2/TR/NC  [ESD0402]
FB1  600R/100M  [L0603]
J36  PJ-327F  [PJ327F]
J37  PH-2.0-2P  [PH-2.0-2P]
MIC1  Micphone  [MIC6050]
R20  1M  [R0402]
R23  47K  [R0402]
R25  NC/100K  [R0402]
R26  0R  [R0402]
R157  0R  [R0402]
R179  1M  [R0402]
R181  NC/100K-1%  [R0402]
R191  10K  [R0402]
R192  10K  [R0402]
R193  10K  [R0402]
R194  10K  [R0402]
R195  1K  [R0402]
R196  1K  [R0402]
R282  1K  [R0402]
RA1  0R  [R0402]
RA2  0R  [R0402]
RA5  1K  [R0402]
RA6  220K  [C0402]
RA7  1.5K  [R0402]
RA8  0R  [R0402]
RA9  0R  [R0402]
RA10  NC  [R0402]
RA11  1.5K  [R0402]
RA12  NC  [R0402]
RA13  1K  [R0402]
RA14  NC  [R0402]
RA15  0R  [R0402]
RA16  0R  [R0402]
RA17  NC  [R0402]
RA18  0R  [R0402]
RA20  NC  [R0402]
RA22  47K  [R0402]
RA26  0R  [R0402]
RA27  2K  [R0402]
RA28  2K  [R0402]
RA29  2K  [R0402]
RA61  2K-1%  [R0402]
RA62  20K-1%  [R0402]
RA63  20K-1%  [R0402]
RA65  2K-1%  [R0402]
RA79  0R  [R0402]
RA80  0R  [R0402]
RA100  33R  [R0402]
RA101  33R  [R0402]
RA102  0R  [R0402]
RA103  0R  [R0402]
RN1  NC/0R  [R0402]
RN2  NC/0R  [R0402]
U6  NS4160  [ESOP-8]
UA1  AC101  [QFN40]
sheet 07 4G
CON2  miniPCIe  [MINI_PCIEX1-52P-5.2H]
D52  DEULC0524PC  [DFN2510-10_L2.5-W1.0-P0.50-BL]
D53  GREEN  [D0603]
J8  NANO-SIM-7P  [NANO-SIM-7P]
R100  10K  [R0402]
R101  2K  [R0402]
sheet 08  UART/485
C35  10uF  [C0603]
C36  0.1uF  [C0402]
C37  0.01uF  [C0402]
D54  1N5819  [SOD323]
D58  DEULC0524PC  [RCLAMP0524P]
D114  SODJ5.0CA  [SOD123]
D115  SODJ5.0CA  [SOD123]
D116  SODJ5.0CA  [SOD123]
J6  XH-2.54-2P  [XH-2.54-2P]
J22  XH-2.54-4P  [XH-2.54-4P]
J38  XH-2.54-4P  [XH-2.54-4P]
Q3  9012  [SOT23]
R42  470R/1%  [R0402]
R43  100R  [R0402]
R44  1K  [R0402]
R45  2K  [R0402]
R46  NC  [R0402]
R47  1K  [R0402]
R48  470R/1%  [R0402]
R49  0R  [R0402]
U4  SP3485CN  [SO8]
sheet 09 IO/ADC/BEEP
D88  DEU0501P1  [ESD0402]
D90  DEU0501P1  [ESD0402]
D91  DEULC0524PC  [RCLAMP0524P]
D93  1N5819  [SOD323]
J7  BEEP_9042  [BEEP_9042]
J30  XH-2.54-7P  [XH-2.54-7P]
Q4  3904  [SOT23]
R51  1K  [R0402]
sheet 10 Ethernet
C81  0.1uF/50V  [C0402]
CE4  0.1uF  [C0402]
CE5  0.1uF  [C0402]
CE7  10uF  [C0603]
CE8  0.1uF  [C0402]
CE9  0.1uF  [C0402]
CE11  0.1uF  [C0402]
CE12  0.1uF  [C0402]
CE13  0.1uF  [C0402]
CE14  0.1uF  [C0402]
CE15  4.7uF  [C0402]
CE17  27PF  [C0402]
CE18  27PF  [C0402]
CE19  0.1uF  [C0402]
CE20  0.1uF  [C0402]
CE21  0.1uF  [C0402]
FB2  100R  [L0603]
J5  HY911130A  [HY911130A]
L3  4.7uH-1A  [SML2520_1P2H/4]
R79  1K  [R0402]
R81  1K  [R0402]
R109  22R/NC  [R0402]
R149  4K7  [R0402]
R150  4K7  [R0402]
RE5  0R  [R0402]
RE7  0R  [R0402]
RE9  0R  [R0402]
RE14  0R  [R0402]
RE15  0R  [R0402]
RE18  4K7  [R0402]
RE20  4K7  [R0402]
RE21  1K5  [R0402]
RE22  2.49K-1%  [R0402]
RE23  4K7  [R0402]
RE25  4K7  [R0402]
RE34  4K7  [R0402]
RE36  4K7  [R0402]
RE38  4K7  [R0402]
RE40  4K7  [R0402]
U15  RTL8211F  [QFN40]
X1  25M-20pF-30ppm  [X3225]
sheet 11 USB3.0/host
C173  4.7uF  [C0402]
C174  10uF  [C0603]
C175  0.1uF  [C0402]
C176  10uF  [C0603]
C177  0.1uF  [C0402]
C178  0.1uF  [C0402]
C179  10uF  [C0603]
C180  0.1uF  [C0402]
C213  0.1uF  [C0402]
C214  0.1uF  [C0402]
C220  0.1uF  [C0402]
CU1  1uF  [C0402]
CU2  10uF  [C0603]
CU3  0.1uF  [C0402]
CU7  10uF-16V  [C0603]
D6  DEU0501P1  [ESD0402]
D7  DEU0501P1  [ESD0402]
D8  DEU0501P1  [ESD0402]
D9  DEU0501P1  [ESD0402]
D10  DEU0501P1  [ESD0402]
D11  DEU0501P1  [ESD0402]
D12  DEULC0524PC  [DFN2510-10_L2.5-W1.0-P0.50-BL]
D13  DEULC0524PC  [DFN2510-10_L2.5-W1.0-P0.50-BL]
D67  DEU0501P1  [ESD0402]
D70  DEU0501P1  [ESD0402]
D71  DEU0501P1  [ESD0402]
D72  DEU0501P1  [ESD0402]
D73  DEU0501P1  [ESD0402]
D74  DEU0501P1  [ESD0402]
D75  DEU0501P1  [ESD0402]
D117  PTVSHC3N24VUP  [DFN-3_2X2]
D170  DEU0501P1  [ESD0402]
D171  DEU0501P1  [ESD0402]
D173  1N5819  [SOD323]
J16  Type-C-SMD  [USB-C-SMD-24P]
LU1  NC/CMF1210UD900MFR  [0805]
LU2  NC/CMF1210UD900MFR  [0805]
LU3  NC/CMF1210UD900MFR  [0805]
LU4  NC/CMF1210UD900MFR  [0805]
LU5  NC/CMF1210UD900MFR  [0805]
Q8  BAT54CW-KL7  [SOT23]
R291  10K  [R0402]
RU1  6K8/1%  [R0402]
RU6  10K  [R0402]
RU7  100K  [R0402]
RU19  5R1  [R0402]
RU22  5R1  [R0402]
RU23  100K  [R0402]
RU24  100K  [R0402]
RU25  2M  [R0402]
RU108  0R  [R0402]
RU109  0R  [R0402]
RU110  2M  [R0402]
RU111  0R  [R0402]
RU112  0R  [R0402]
RU113  0R  [R0402]
RU114  0R  [R0402]
RU116  0R  [R0402]
RU119  0R  [R0402]
U3  SY6280  [SOT23-5]
U10  SL2.1S  [SSOP16_SL2.1S]
U11  CH340E  [MSOP-10]
U14  PI3USB4000AZUAEX  [UQFN-10_L2.0-W1.5-P0.50-BL]
USB4  USB-A-3.0X2-90  [USB-A-3.0X2-90]
X3  12MHz  [X3225]
sheet 12 HDMI
D85  SS14  [SOD123]
D86  SS14  [SOD123]
D87  DEU0501P1  [ESD0402]
DE1  DEULC0524PC  [DFN2510-10_L2.5-W1.0-P0.50-BL]
Q1  BSN20  [SOT23]
R27  27K/1%  [R0402]
R28  27K/1%  [R0402]
R29  20K/1%  [R0402]
R30  2K  [R0402]
R31  2K  [R0402]
R32  27K/1%  [R0402]
U16  DEULC0524PC  [DFN2510-10_L2.5-W1.0-P0.50-BL]
U17  HDMI_19plug_A  [HDMIQ]
U18  DEULC0524PC  [DFN2510-10_L2.5-W1.0-P0.50-BL]

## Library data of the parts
C139-C144 C181-C184 C226 CA3 CA5-CA7 CA9 CA12 CA83-CA89 CA91 = C-C0402: Parameter: C0402-X5R
FID1-FID5 = T_POINT_R_2: FIDUCAL MARK; COMPONENT_WEIGHT: 30
H1-H4 H6 H7 = T_POINT_R_1: HOLE
R8 R9 R65 R69 R76 R77 = R-R0402-1%
R4 R6 R7 R10 R11 R29 R51 R79 R81 R100 R101 R109 R149 R150 R165 R166 R199 R201-R208 R213-R218 R266 R267 R289-R291 R293-R298 = R
R234 R235 R278-R281 = R1_0805
TP0 TP3 = T_POINT_R_1
U64 = AO4409_18
C2 C75 = CAPACITOR_0_v3
C5-C7 C73 = CAPACITOR
C71 = CAP-T-33uF-C-16V: TEN: <TEN>
C3 C81 C90 C190 C235 = CAPACITOR_0
C92 C94 C191 C193 = CAP_NP_3: cap,100.00nF,+/-10%,25V,X5R,C0402; Created by: JJJ; Dielectric: X5R; Priority: A; Tolerance: 10%; Voltage: 25V
C93 C192 = CAP_NP_3: cap,100.00pF,+/-5%,50V,C0G,C0402; Created by: JJJ; Dielectric: C0G; Priority: A; Tolerance: 5%; Voltage: 50V
C95 = CAP_NP_3: cap,100.00nF,+/-10%,16V,X5R,C0402; Created by: JJJ; Dielectric: X5R; Priority: A; Tolerance: 10%; Voltage: 16V
C96 C97 = CAP_NP_3: cap,22.00uF,+/-10%,10V,X5R,C0805; Created by: JJJ; Dielectric: X5R; Priority: A; Tolerance: 10%; Voltage: 10V
C88 C89 C223 C224 = CAP_NP_0: Status: Taiwan
D2 = DIODE_TVS_BI-DIR
D3 = LED_0
F1 = FUSE_1
J1 = PHONOJACK_3: ￠3.5DC电源座　前插后贴　5PIN，两定位柱，高4.7mm; PART NUMBER: ZDC-BCT05-1000; SPREADWIN PN: E10000040A; Vendor: 质友
J2 = CON3
J41 = CON2_0
L1 L2 = ind1: Power Inductor,3.3uH,0.2,IND_404030; Created by: YTL; DC Resistor: 0.04ohm; Irms: 2.4A; Isat: 3.3A; Priority: A; Resonace frequency: 38M; Tolerance: 20%
L5 = INDUCTOR_IRON
R2 R5 R158 R159 R173 R174 R292 = RESISTOR_1: RES,thick film,47KOhm,+/-5%,1/16W,SMD0402
R27 R28 R30-R32 R37 R38 R59-R62 R209 R210 = RESISTOR
U2 U12 = DCDC_SY8113: Created by: JJJ; Priority: A
U5 = SGM2028_0
U28 = XC9235_0
CON1 = CON39PIN_0
CP5-CP8 = C-C0603-X5R_1: Parameter: C0402-X5R
D26-D28 D30-D35 D39 D40 D47 D49 D52 D58 D91 DE1 U16 U18 = rRClamp0524P
D1 D4 D5 D41-D45 D67 D70-D75 D87 D88 D90 D126-D130 D170-D172 D174-D178 = 1_1.5KE100A: 1ST PART DESCRIPTION: WILL ESD9B5V Bidirection ESD Protection
C53-C55 C57 C58 C60 C215 C216 C234 = C_v2
C59 C230-C233 = CAP_POL
C91 = C
D46 D54 D93 D125 D173 = BAS21_SOT_1
D81 D83 = BAT54S_SOT
D82 D84 = DIODE_BREAKDOWN_1
J3 = HEADER_20X2_1: Populate: YES
J10 = connet_0
J39 = HEADER_20X2_3: Populate: YES
J40 = CON4_4
L4 = INDUCTOR_v2
L7 = CHOKE_TORROID-FERRITE
U13 = PT4110_0
U63 = X9C102_SO_2
C4 = CAPACITOR_0: PAGE: 2
J4 = SDMMC_SLOT_0
J14 = CON6_0
J42 = CON2
K1-K4 = SW_PUSHBUTTON
C69 C70 C111 C197 CE4 CE5 CE7-CE9 CE11-CE15 CE17-CE21 = C-C0402
C72 = CAPACITOR_0: options: 4890-2
CA1 CA2 CA10 CA11 CA18 = CAPACITOR_0: PAGE: 2; ROOM: POWER
CA4 CA13 CA14 CA17 CA23 CA25 CA26 = CAPACITOR_0: PAGE: 1; ROOM: AC100
CA8 = C-C0603: Parameter: C0402-X5R
D6-D11 D15-D19 = ESD9B5VL
D20 D118 = ESD9B5VL: options: 4890-1
DA1 DA2 = ESD9B5VL_0
FB1 FB2 = INDUCTOR_0_v2: RoHS BEAD/600ohm 100Mhz Z=600Ω DCR<0.2Ω 800mA SMT L0603; Package: SMT; Pin Names Rotate: TRUE; Pin Names Visible: FALSE; Pin Numbers Visible: TRUE
J36 = PJ381-2_1
J37 = SPEAKER_0
MIC1 = Micphone_0: mypage: 13
R20 R23 R25 R26 R157 R179 R181 R195 R196 R282 RA1 RA2 RA5 RA7 RA11 RA13 RA79 RA80 RA100 RA101 RE5 RE7 RE9 RE14 RE15 RE18 RE20-RE23 RE25 RE34 RE36 RE38 RE40 RN1 RN2 RU19 RU22-RU25 RU108-RU114 RU116 RU119 = R-R0402-5%
R191-R194 = RESISTOR: options: 4890-2
RA6 RA8-RA10 RA12 RA14-RA18 RA20 RA22 RA26-RA29 RA102 RA103 = R: ROOM: AC100
RA61-RA63 RA65 = R-R0603-1%
U6 = LY8006_1
UA1 = AC101&AC101B_V0_1.2
CON2 = CON50A_5
D53 = LED
J8 = SIM-7P_0
C35 = C0603
C36 = C0402
C37 = C0402_1
D114-D116 = ESD_DIODE: TVS diode;DC Working Voltage(VDC):16.0V;Clamping Voltage(VCL)Ipeak = 1A,8/20£gs:290V Maximum;Capacitance(C)@1MHz, 1V:2pF Typic
J6 = CON4_3_v2
J22 J38 = CON4
Q3 = 2N3906_0
R42 = R0402_3
R43 = R0402_6
R44 = R0402_7
R45 = R0402_1
R46 = R0402
R47 = R0402_5
R48 = R0402_4
R49 = R0402_2
U4 = SP3485
J7 = CON2_0_v2
J30 = CON4_2
Q4 = 2N3904_0
J5 = HY911130A
L3 = L-L2016
U15 = 8211F
X1 = 3224
C173 = CAP_NP_8
C174 = CAP_NP_7
C175 = CAP_NP_6
C176 = CAP_NP_5
C177 = CAP_NP_4
C178 = CAP_NP_3
C179 = CAP_NP_1
C180 = CAP_NP
C213 C214 = C-0402_0
C220 = CAP_NP_2
CU1 CU3 = C-C0402: PAGE: 2; ROOM: EMMC; mypage: 08
CU2 CU7 = C-C0603
D12 D13 = ESD_ESD5304D: 4-Lines, Uni-directional, Ultra-low Capacitance Transient Voltage Suppressors; Created by: JJJ; Manufacturer: WillSemi(韦尔半导体); Manufacturer PN: ESD5304D; Part Type: ESD_TVS; Priority: A; RK PN: ESD5304D
D117 = DIODE_SCHOTTKY_6: RoHS 1.0 Ampere Schottky Barrier Rectifiers  SOD-123; Material code: 1902-PTVSHC34-0114; OPTIONS: TLL
J16 = Type-C-CSTU-16022400E_0
LU1-LU5 = ICMS212B900MFR_0
Q8 = PNP_DIAC_0
RU1 RU6 RU7 = R-R0402-5%: ROOM: EMMC; mypage: 08
U3 = SY6280
U10 = MW7220_QFP64_1
U11 = CH340G_1
U14 = MW7220_QFP64_2
USB4 = USB_1: USB Receptacle; Manufacturer: MPS; Mfg #1: KEMET; Part Type: connetc; Toler.: 10%; Voltage: 2000V; Watts: 0.1W
X3 = XTAL_HC49LP_27MHz_MK2743_4
D85 D86 = D_0: Allegro PCB Footprint: d2513A
Q1 = NMOS_0
U17 = HDMI_A

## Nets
3V3-EN: R37.2 U28.1(EN) U64.173(PL3/S-UART1-RX/S-UART0-RX/S-TWI1-SCK/S-IR-RX/S-PWM0-1/PL-EINT3)
5V: C6.1 C35.1 C36.1 C93.1 C95.1 C96.1 C97.1 C216.1 C223.2 C234.1 CU1.2 D3.1(ANODE) D85.1 D114.2(CATHODE) FB1.2 J3.37 J3.38 L1.2 L4.1 L7.1 R2.1 R42.1 R201.1 R202.1 R210.2 R293.1 U3.5(IN) U4.8(VCC) U5.3(VIN) U13.6(IN) U28.4(VIN) U63.5(VIN)
5V-IN: R293.2 U64.163(5V-IN) U64.164(5V-IN)
AVCC: R20.1 R234.1 R278.1 R280.1 U64.182(AVCC)
AVDD: C54.1 C59.1 C230.1 D81.1 D125.2(CATHODE) J39.29(AVDD) R199.1 R207.2
AVDD10: CE4.2 CE5.2 CE7.2 CE8.2 CE20.2 CE21.2 L3.2 U15.3(AVDD10) U15.8(AVDD10) U15.21(DVDD10) U15.38(AVDD10)
AVDD33: CE9.2 CE11.2 CE12.2 CE13.2 CE14.2 CE15.2 FB2.2 R81.2 R149.1 RE18.1 RE20.1 RE21.1 RE25.2 RE36.2 RE38.2 RE40.2 U15.11(AVDD33) U15.28(DVDD_RG) U15.29(DVDD33) U15.40(AVDD33)
AVDD-CSI: CON1.38(AVDD28) CP7.1 D177.2(CATHODE) R8.1 R9.1 U64.36(AVDD-CSI)
DVDD-CSI: CON1.37(DVDD) CP6.1 D176.2(CATHODE) U64.35(DVDD-CSI)
GND: C2.2 C3.2 C4.1 C5.2 C6.2 C54.2 C55.2 C58.2 C59.2 C60.2 C69.2 C70.2 C71.2(M) C73.2 C75.2 C81.1 C90.2 C91.2 C94.2 C95.2 C96.2 C97.2 C173.2 C174.2 C175.2 C176.2 C177.2 C178.2 C179.2 C180.2 C183.2 C184.2 C190.2 C193.2 C197.2 C215.2 C216.2 C220.2 C223.1 C224.1 C226.1 C230.2 C231.1 C232.2 C233.2 C234.2 C235.1 CA1.1 CA2.2 CA3.1 CA4.1 CA5.1 CA10.2 CA11.2 CA12.2 CA13.2 CA14.2 CA17.2 CA18.1 CA23.2 CA25.2 CA83.1 CA89.2 CE4.1 CE5.1 CE7.1 CE8.1 CE9.1 CE11.1 CE12.1 CE13.1 CE14.1 CE15.1 CE17.1 CE18.1 CE19.1 CE20.1 CE21.1 CON1.1(GND0) CON1.4(GND1) CON1.7(GND2) CON1.10(GND3) CON1.13(GND4) CON1.16(GND5) CON1.19(GND6) CON1.22(GND7) CON1.25(GND8) CON1.27(GND9) CON1.29(GND10) CON1.40 CON1.41 CON2.4(GND1) CON2.9(GND2) CON2.15(GND3) CON2.18(GND4) CON2.21(GND5) CON2.26(GND6) CON2.27(GND7) CON2.29(GND8) CON2.34(GND9) CON2.35(GND10) CON2.37(GND11) CON2.40(GND12) CON2.43(GND13) CON2.M1 CON2.M2 CP5.2 CP6.2 CP7.2 CP8.2 CU1.1 CU2.1 CU3.1 CU7.2 D1.2(CATHODE) D2.1 D4.1(ANODE) D5.1(ANODE) D6.2(CATHODE) D7.2(CATHODE) D8.2(CATHODE) D9.2(CATHODE) D10.2(CATHODE) D11.2(CATHODE) D12.3(GND) D12.8(GND) D13.3(GND) D13.8(GND) D15.1(ANODE) D16.1(ANODE) D17.1(ANODE) D18.1(ANODE) D19.1(ANODE) D20.1(ANODE) D26.3(GND1) D26.8(GND2) D27.3(GND1) D27.8(GND2) D28.3(GND1) D28.8(GND2) D30.3(GND1) D30.8(GND2) D31.3(GND1) D31.8(GND2) D32.3(GND1) D32.8(GND2) D33.3(GND1) D33.8(GND2) D34.3(GND1) D34.8(GND2) D35.3(GND1) D35.8(GND2) D39.3(GND1) D39.8(GND2) D40.3(GND1) D40.8(GND2) D41.2(CATHODE) D42.2(CATHODE) D43.2(CATHODE) D44.2(CATHODE) D45.2(CATHODE) D47.3(GND1) D47.8(GND2) D49.3(GND1) D49.8(GND2) D52.3(GND1) D52.8(GND2) D58.3(GND1) D58.8(GND2) D67.1(ANODE) D70.2(CATHODE) D71.2(CATHODE) D72.2(CATHODE) D73.2(CATHODE) D74.2(CATHODE) D75.2(CATHODE) D82.1(ANODE) D83.2 D84.2(CATHODE) D87.2(CATHODE) D88.2(CATHODE) D90.2(CATHODE) D91.3(GND1) D91.8(GND2) D117.3 D118.1(ANODE) D126.1(ANODE) D127.1(ANODE) D128.1(ANODE) D129.1(ANODE) D130.2(CATHODE) D170.2(CATHODE) D171.2(CATHODE) D172.1(ANODE) D174.1(ANODE) D175.1(ANODE) D176.1(ANODE) D177.1(ANODE) D178.1(ANODE) DA1.1(ANODE) DA2.1(ANODE) DE1.3(GND1) DE1.8(GND2) FID4.1(TP) J1.2 J1.3 J2.3 J3.5 J3.6 J3.7 J3.8 J3.15 J3.16 J3.23 J3.24 J3.31 J3.32 J4.6(VSS2) J4.10(GND) J4.11(GND1) J4.12(GND2) J4.13(GND3) J5.10(CHSGND) J5.12(GREEN-) J8.5(GND) J8.8(GND) J8.9(GND) J8.10(GND) J8.11(GND) J10.3 J14.1 J16.1(Shield1) J16.2(Shield2) J16.3(Shield3) J16.4(Shield4) J16.A1(GND2) J16.A12(GND1) J16.B1(GND4) J16.B12(GND3) J22.4 J30.6 J38.4 J39.7(GND) J39.10(GND) J39.13(GND) J39.16(GND) J39.19(GND) J39.22(GND) J39.25(GND) J39.28(SELB(HSD)) J39.30(GND) J40.4 J40.5 J40.6 J41.2 J41.3 J42.2 K1.2 K2.1 K3.1 K4.2 Q4.2(EMITTER) R4.1 R5.2 R6.2 R25.2 R26.2 R32.2 R37.1 R38.1 R49.2 R60.1 R62.1 R150.1 R159.2 R165.1 R166.1 R174.2 R179.1 R203.2 R204.2 R205.2 R208.2 R215.2 R216.2 R217.2 R218.2 R235.2 R266.2 R279.2 R281.2 R289.2 R292.2 RA6.1 RA8.2 RA13.2 RA26.2 RA61.2 RA65.1 RE22.1 RE23.1 RE34.1 RU1.1 RU7.1 RU25.2 RU110.2 U2.2(GND) U3.2(GND) U5.1(GND) U6.7(GND) U6.9(GND) U10.8(VSS) U11.3(GND) U12.2(GND) U13.2(GND) U14.5(GND) U14.6(EN#) U15.41(EGND) U16.3(GND1) U16.8(GND2) U17.2(D2_Shield) U17.5(D1_Shield) U17.8(D0_Shield) U17.11(CK_Shield) U17.17(DDC/CEC_GND) U17.20(SHIELD1) U17.21(SHIELD2) U17.22(SHIELD3) U17.23(SHIELD4) U18.3(GND1) U18.8(GND2) U28.2(VSS) U63.2(GND) U64.38(GND) U64.95(GND) U64.158(GND) U64.162(GND) U64.165(GND) U64.188(GND) UA1.41(GND) USB4.4(GND1) USB4.7(GND_DRAIN1) USB4.13(GND2) USB4.16(GND_DRAIN2) USB4.19(Shield) USB4.20(Shield) USB4.21(Shield) USB4.22(Shield) X1.2 X1.4
GND_485: C35.2 C36.2 D115.1(ANODE) R45.2 R48.1 R49.1 U4.5(GND)
VBUS1: CU2.2 CU3.2 D67.2(CATHODE) U3.1(OUT) USB4.1(VBUS1) USB4.10(VBUS2)
VBUS-EN-PL13: RU7.2 U3.4(EN) U64.170(PL13/S-UART1-RX/S-TWI1-SDA/S-TWI2-SDA/PL-EINT13)
VBUS-USB: C179.1 C180.1 CU7.1 D117.1 D117.2 J16.A4(VBUS1) J16.A9(VBUS2) J16.B4(VBUS3) J16.B9(VBUS4) U10.7(VDD5)
VCC-1V8: C224.2 R295.1 R296.1 R297.1 R298.1 RA103.1 U5.2(VOUT)
VCC-3V3: C2.1 C4.2 C5.1 C7.1 C37.1 D86.1 D90.1(ANODE) D93.2(CATHODE) D129.2(CATHODE) FB2.1 J4.4(VDD) J7.1 J10.2 J22.1 J30.7 J38.1 J39.2(VDD) J39.3(VDD) J41.4 L5.2 Q1.1(GATE) Q3.2(EMITTER) Q8.2(EMITTER) R7.2 R10.1 R11.1 R27.2 R44.2 R206.1 R213.2 R214.2 R267.1 R290.1 R291.2 RA27.2 RA28.2 RA29.1 RA102.1
VCC_4G: C71.1(P) C73.1 C75.1 C192.1 CON2.2(VDD_3V3A) CON2.24(VDD_3V3B) CON2.39(VDD_3V3C) CON2.41(VDD_3V3D) CON2.52(VDD_3V3E) D53.1(ANODE) L2.2 R100.2 R173.1
VPP/VCC: CA10.1 RA9.2 RA10.1 UA1.15(VPP/VCC)
VRN/AGND: RA26.1 UA1.6(VRN/AGND)
VRP/AVCC: CA1.2 UA1.5(VRP/AVCC)
4G-EN-PL12: R292.1 U12.4(EN) U64.171(PL12/S-UART1-TX/S-TWI1-SCK/S-TWI2-SCK/S-IR-RX/PL-EINT12)
340_3V3: C174.1 C175.1 C176.1 C177.1 C178.1 Q8.1(COLLECTOR) U10.9(VDD33) U11.7(VCC) U11.10(V3)
485_1+: D115.2(CATHODE) D116.1(ANODE) J6.2 R42.2 R46.2 U4.6(A)
485_1-: D114.1(ANODE) D116.2(CATHODE) J6.1 R46.1 R48.2 U4.7(B)
AECRN: CA87.2 RA80.1
AECRP: CA84.2 RA79.1
AFVCC-CSI: CON1.36(AF_VDD28) CP5.1 D175.2(CATHODE) U64.34(AFVCC-CSI)
AGND/VRP: RA8.1 UA1.7(AGND/VRP)
AP-RESET: D5.2(CATHODE) K3.2 U64.167(RESET)
AUXN: C144.2 D9.1(ANODE) J16.B8(SBU2) RU24.2 RU110.1
AUXP: C143.2 D8.1(ANODE) J16.A8(SBU1) RU23.2 RU25.1
AVCC/VRA1: CA14.1 RA16.2 UA1.8(AVCC/VRA1)
CC1: D10.1(ANODE) J16.A5(CC1)
CC2: D11.1(ANODE) J16.B5(CC2)
CLKOUT-125M: RE15.2 U15.35(CLKOUT)
CODEC-AVCC: CA18.2 RA10.2 RA14.1 RA16.1 RA17.2 RA102.2 UA1.25(VDD-IO) UA1.33(VCC-IO/DEVID)
CODEC-CPVDD: RA9.1 RA15.1 RA18.1 RA103.2
CODEC-IRQ: RA29.2 U64.108(PB2/UART2-RTS/SPI2-MOSI/HDMI-SCL/LCD0-D8/JTAG-DO/TWI0-SCK/PB-EINT2) UA1.24(IRQ)
CODEC-RST: RA20.2 U64.109(PB3/UART2-CTS/SPI2-MISO/HDMI-SDA/LCD0-D9/JTAG-DI/TWI0-SDA/PB-EINT3)
COMB1-REFN: R165.2 U64.128(COMB1-REF-CLKN)
COMB1-REFP: R166.2 U64.127(COMB1-REF-CLKP)
COMB1-RX0N: D72.1(ANODE) U64.126(PCIE1-RX0N/USB2-U3-RX0N) USB4.14(RX2-)
COMB1-RX0P: D73.1(ANODE) U64.125(PCIE1-RX0P/USB2-U3-RX0P) USB4.15(RX2+)
COMB1-TX0N: C213.1 U64.122(PCIE1-TX0N/USB2-U3-TX0N)
COMB1-TX0P: C214.1 U64.121(PCIE1-TX0P/USB2-U3-TX0P)
CPVDD: CA13.1 RA15.2 UA1.22(CPVDD)
CTP0-INT: D47.5(IN4) D47.6(OUT4) J3.3 J10.4 R213.1 U64.180(PL10/S-UART0-TX/S-TWI2-SCK/S-UART1-TX/S-PWM0-8/PL-EINT10)
CTP0-RST: D47.4(IN3) D47.7(OUT3) J3.4 J10.1 U64.181(PL11/S-UART0-RX/S-TWI2-SDA/S-UART1-RX/S-IR-RX/S-PWM0-9/PL-EINT11)
D+: D6.1(ANODE) J16.A6(D2+) J16.B6(D1+) LU2.1 RU19.2
D-: D7.1(ANODE) J16.A7(D2-) J16.B7(D1-) LU2.2 RU22.2
DC_EN: J2.2 R5.1 R158.2 U2.4(EN)
DCIN: C90.1 C94.1 C190.1 C193.1 D2.2 F1.2 J41.1 R158.1 U2.5(VIN) U12.5(VIN)
FEL: D1.1(ANODE) K1.1 U64.145(FEL)
GPADC4: R234.2 R235.1 U64.155(GPADC4)
GPADC5: R278.2 R279.1 U64.156(GPADC5)
GPADC6: R280.2 R281.1 U64.157(GPADC6)
HBIAS: C226.2 R282.2 UA1.2(HBIAS)
HCEC: Q1.2(SOURCE) R27.1 U64.39(HCEC)
HDMI-5V: D85.2 D87.1(ANODE) R30.2 R31.2 U17.18(+5V)
HDMI-HCEC: Q1.3(DRAIN) R28.2 U17.13(CEC) U18.1(IN1) U18.10(OUT1)
HHPD: R29.1 R32.1 U64.40(HHPD)
HHPD1: R29.2 U17.19(HPD) U18.5(IN4) U18.6(OUT4)
HP-DET: R23.1 RA12.2 RA14.2 RA22.1
HP-DET-PE11: RA22.2 U64.129(PE11/TWI4-SDA/SPI3-MISO/I2S3-DIN2/I2S3-DOUT2/PCIE-CLKREQN/NCSI0-D7/UART1-CTS/PE-EINT11)
HPOUTFB-1: D16.2(CATHODE) J36.2(G/M) RA2.2 RN1.2
HPOUTFB-2: C183.1 CA91.2 R26.1 R196.2 RA2.1 RN2.1 UA1.18(HPOUTFB)
HPOUTL-2: C88.2 UA1.17(HPOUTL)
HPOUTR-2: C89.2 UA1.19(HPOUTR)
HS-MIC-1: D15.2(CATHODE) J36.5(M/G) RA1.2 RN2.2
HS-MIC-2: C184.1 CA91.1 R195.2 R282.1 RA1.1 RN1.1
HSCL: R30.1 U17.15(DDC_SCL) U18.2(IN2) U18.9(OUT2) U64.42(HSCL)
HSDA: R31.1 U17.16(DDC_SDA) U18.4(IN3) U18.7(OUT3) U64.41(HSDA)
HTX0N: U16.2(IN2) U16.9(OUT2) U17.9(D0-) U64.45(HTX0N)
HTX0P: U16.1(IN1) U16.10(OUT1) U17.7(D0+) U64.46(HTX0P)
HTX1N: DE1.5(IN4) DE1.6(OUT4) U17.6(D1-) U64.47(HTX1N)
HTX1P: DE1.4(IN3) DE1.7(OUT3) U17.4(D1+) U64.48(HTX1P)
HTX2N: DE1.2(IN2) DE1.9(OUT2) U17.3(D2-) U64.49(HTX2N)
HTX2P: DE1.1(IN1) DE1.10(OUT1) U17.1(D2+) U64.50(HTX2P)
HTXCN: U16.5(IN4) U16.6(OUT4) U17.12(CK-) U64.43(HTXCN)
HTXCP: U16.4(IN3) U16.7(OUT3) U17.10(CK+) U64.44(HTXCP)
HUB1-DM3: U10.15(DM3) U11.2(UD-)
HUB1-DP3: U10.16(DP3) U11.1(UD+)
I2S0-BCLK: U64.111(PB5/I2S0-BCLK/SPI2-CS2/PWM0-1/LCD0-D17/TRACE-DATA0/TWI1-SDA/PB-EINT5) UA1.29(BCLK)
I2S0-DIN0: U64.114(PB8/CLK-FANOUT3/I2S0-DIN0/I2S0-DOUT1/PWM1-0/OWA0-OUT/TRACE-DATA3/TWI1-SDA/PB-EINT8) UA1.27(SDOUT)
I2S0-DOUT0: U64.113(PB7/CLK-FANOUT2/I2S0-DOUT0/I2S0-DIN1/PWM0-9/OWA0-IN/TRACE-DATA2/TWI1-SCK/PB-EINT7) UA1.26(SDIN)
I2S0-LRCK: U64.112(PB6/CLK-FANOUT1/I2S0-LRCK/SPI2-CS3/PWM0-2/PWM0-8/TRACE-DATA1/PB-EINT6) UA1.28(LRCK)
I2S0-MCLK: U64.110(PB4/PWM0-0/I2S0-MCLK/SPI2-CS1/HDMI-CEC/LCD0-D16/TRACE-CLK/TWI1-SCK/PB-EINT4) UA1.30(MCLK)
INTB: RE20.2 U15.31(INTB/PMEB)
IO-RESET: D130.1(ANODE) K4.1 R298.2 U64.6(PK19/MCSIB-D3P/MCSI2-MCLK/UART2-CTS/PWM1-2/NCSI1-D0/TWI9-SDA/PK-EINT19)
IOVDD-CSI: CON1.39(DOVDD18) CP8.1 D178.2(CATHODE) U64.37(IOVDD-CSI)
LCD0-EN: D41.1(ANODE) J3.40 R209.2 U64.81(PD23/PWM0-5/PCIE-CLKREQN/TWI0-SDA/TWI2-SDA/PWM1-5/PD-EINT23)
LCD0-HSYNC: D44.1(ANODE) J3.29 U64.78(PD20/LCD0-HSYNC/DSI-TRIG-LCD-TE1/TWI0-SCK/EINK-CKV_/PCIE-CLKREQN/UART4-TX/TWI3-SCK/PWM0-2/PD-EINT20)
LCD0-PWM: D42.1(ANODE) J3.39 R215.1 U13.4(~{SHDN}) U64.80(PD22/PWM0-4/EINK-STV/PCIE-PERSTN/TWI0-SCK/TWI2-SCK/PWM1-4/PD-EINT22)
LCD0-VSYNC: D43.1(ANODE) J3.30 U64.79(PD21/LCD0-VSYNC/TWI0-SDA/EINK-MODE/PCIE-WAKEN/UART4-RX/TWI3-SDA/PWM0-3/PD-EINT21)
LCD-PE3: J40.1 R295.2 U64.7(PE3/TWI3-SCK/CSI1-XVS-FSYNC/PWM0-0/SPI3-MISO/LPC-LFRAME/NCSI0-D1/UART6-CTS/PE-EINT3)
LCD-PE4: J40.2 R296.2 U64.8(PE4/TWI3-SDA/LEDC/PWM0-1/SPI3-CS1/LPC-LSMI/NCSI0-D0/UART6-DCD/PE-EINT4)
LCD-PE5: J40.3 R297.2 U64.9(PE5/MCSI1-MCLK/PLL-LOCK-DBG/PWM0-2/LPC-LCLK/NCSI0-MCLK/UART6-DSR/PE-EINT5)
LCD_LR: J39.33(L/R) R201.2 R203.1
LCD_RST-PL7: C235.2 D45.1(ANODE) J39.5(RESET) R290.2 U64.177(PL7/S-JTAG-DI/S-UART0-RX/S-SPI0-MISO/S-PWM0-5/PL-EINT7)
LCD_UD: J39.34(U/D) R202.2 R204.1
LDOIN/RSTN: CA17.1 RA17.1 RA18.2 RA20.1 UA1.36(LDOIN/RSTN)
LED0_AD0: J5.13(YELLOW-) R149.2 U15.32(LED0/CFG_EXT)
LED1_AD1: R79.2 R150.2 U15.33(LED1/CFG_LDO0)
LED+: C91.1 C215.1 D46.2(CATHODE) J39.39(LED+) J39.40(LED+) U13.5(OVP)
LED-: J39.31(LED-) J39.32(LED-) R6.1 R216.1 R217.1 R218.1 U13.3(FB)
LRADC0: D172.2(CATHODE) J42.1 U64.183(LRADC0)
LVDS0-CKN: D40.1(IN1) D40.10(OUT1) J3.34 J39.17(RXCLKN-) U64.58(PD7/LCD0-D11/LVDS0-CKN/DSI0-D2N/EINK-D7/PWM0-7/PD-EINT7)
LVDS0-CKP: D40.2(IN2) D40.9(OUT2) J3.33 J39.18(RXCLKN+) U64.57(PD6/LCD0-D10/LVDS0-CKP/DSI0-D2P/EINK-D6/PWM0-6/PD-EINT6)
LVDS0-D0N: D33.2(IN2) D33.9(OUT2) J3.10 J39.8(RXIN0-) U64.52(PD1/LCD0-D3/LVDS0-D0N/DSI0-D0N/EINK-D1/PWM0-1/PD-EINT1)
LVDS0-D0P: D33.1(IN1) D33.10(OUT1) J3.9 J39.9(RXIN0+) U64.51(PD0/LCD0-D2/LVDS0-D0P/DSI0-D0P/EINK-D0/PWM0-0/PD-EINT0)
LVDS0-D1N: D33.5(IN4) D33.6(OUT4) J3.12 J39.11(RXIN1-) U64.54(PD3/LCD0-D5/LVDS0-D1N/DSI0-D1N/EINK-D3/PWM0-3/PD-EINT3)
LVDS0-D1P: D33.4(IN3) D33.7(OUT3) J3.11 J39.12(RXIN1+) U64.53(PD2/LCD0-D4/LVDS0-D1P/DSI0-D1P/EINK-D2/PWM0-2/PD-EINT2)
LVDS0-D2N: D34.2(IN2) D34.9(OUT2) J3.14 J39.14(RXIN2-) U64.56(PD5/LCD0-D7/LVDS0-D2N/DSI0-CKN/EINK-D5/PWM0-5/PD-EINT5)
LVDS0-D2P: D34.1(IN1) D34.10(OUT1) J3.13 J39.15(RXIN2+) U64.55(PD4/LCD0-D6/LVDS0-D2P/DSI0-CKP/EINK-D4/PWM0-4/PD-EINT4)
LVDS0-D3N: D40.4(IN3) D40.7(OUT3) J3.36 J39.20(RXIN3-) U64.60(PD9/LCD0-D13/LVDS0-D3N/DSI0-D3N/EINK-D9/PWM0-9/PD-EINT9)
LVDS0-D3P: D40.5(IN4) D40.6(OUT4) J3.35 J39.21(RXIN3+) U64.59(PD8/LCD0-D12/LVDS0-D3P/DSI0-D3P/EINK-D8/PWM0-8/PD-EINT8)
LVDS1-CKN: D39.2(IN2) D39.9(OUT2) J3.26 U64.68(PD17/LCD0-D23/LVDS1-CKN/DSI1-D2N/EINK-LEH/TWI2-SDA/UART3-RX/PD-EINT17)
LVDS1-CKP: D39.1(IN1) D39.10(OUT1) J3.25 U64.67(PD16/LCD0-D22/LVDS1-CKP/DSI1-D2P/EINK-OEH/TWI2-SCK/UART3-TX/PD-EINT16)
LVDS1-D0N: D34.5(IN4) D34.6(OUT4) J3.18 U64.62(PD11/LCD0-D15/LVDS1-D0N/DSI1-D0N/EINK-D11/SPI1-CLK<DBI-SCLK>/PWM1-1/PD-EINT11)
LVDS1-D0P: D34.4(IN3) D34.7(OUT3) J3.17 U64.61(PD10/LCD0-D14/LVDS1-D0P/DSI1-D0P/EINK-D10/SPI1-CS0<DBI-CSX>/PWM1-0/PD-EINT10)
LVDS1-D1N: D35.2(IN2) D35.9(OUT2) J3.20 U64.64(PD13/LCD0-D19/LVDS1-D1N/DSI1-D1N/EINK-D13/SPI1-MISO<DBI-SDI/DBI-TE/DBI-DCX>/PWM1-3/PD-EINT13)
LVDS1-D1P: D35.1(IN1) D35.10(OUT1) J3.19 U64.63(PD12/LCD0-D18/LVDS1-D1P/DSI1-D1P/EINK-D12/SPI1-MOSI<DBI-SDO>/PWM1-2/PD-EINT12)
LVDS1-D2N: D35.5(IN4) D35.6(OUT4) J3.22 U64.66(PD15/LCD0-D21/LVDS1-D2N/DSI1-CKN/EINK-D15/SPI1-CS1/UART3-CTS/PD-EINT15)
LVDS1-D2P: D35.4(IN3) D35.7(OUT3) J3.21 U64.65(PD14/LCD0-D20/LVDS1-D2P/DSI1-CKP/EINK-D14/SPI1-HOLD<DBI-DCX/DBI-WRX>/UART3-RTS/PD-EINT14)
LVDS1-D3N: D39.5(IN4) D39.6(OUT4) J3.28 U64.70(PD19/LCD0-DE/LVDS1-D3N/DSI1-D3N/EINK-STH/PWM1-5/UART4-CTS/PD-EINT19)
LVDS1-D3P: D39.4(IN3) D39.7(OUT3) J3.27 U64.69(PD18/LCD0-CLK/LVDS1-D3P/DSI1-D3P/EINK-CKH/SPI1-WP<DBI-TE>/UART4-RTS/PD-EINT18)
MBIAS: CA5.2 RA5.2 UA1.38(MBIAS)
MCSI0-MCLK: CON1.26(MCLK_F) D28.1(IN1) D28.10(OUT1) U64.26(PE0/MCSI0-MCLK/CSI0-XHS/SPI3-CS0/LPC-LAD0/NCSI0-HSYNC/UART6-TX/PE-EINT0)
MCSI2-MCLK: CON1.28(MCLK_B) D28.2(IN2) D28.9(OUT2) U64.27(PE9/MCSI2-MCLK/TCON-FSYNC0/I2S3-MCLK/LPC-LRESET/NCSI0-D5/UART6-RI/PE-EINT9)
MCSI-RST-F: CON1.31(RESET_F) D28.5(IN4) D28.6(OUT4) U64.29(PE7/CLK-FANOUT2/HDMI-SCL/I2S3-BCLK/LPC-LAD1/NCSI0-D3/TWI11-SCK/PE-EINT7)
MCSI-RST-R: CON1.32(RESET_B) D32.4(IN3) D32.7(OUT3) U64.31(PE10/TWI4-SCK/TCON-FSYNC1/I2S3-DIN3/I2S3-DOUT3/LPC-LAD3/NCSI0-D6/UART1-RTS/PE-EINT10)
MCSI-SCK-TWI2: CON1.34(SCL) D32.2(IN2) D32.9(OUT2) R8.2 U64.32(PE1/TWI2-SCK/CSI1-XHS/SPI3-CLK/LPC-LPME/NCSI0-VSYNC/UART6-RX/PE-EINT1)
MCSI-SDA-TWI2: CON1.35(SDA) D32.1(IN1) D32.10(OUT1) R9.2 U64.33(PE2/TWI2-SDA/CSI0-XVS-FSYNC/SPI3-MOSI/LPC-LPCPD/NCSI0-PCLK/UART6-RTS/PE-EINT2)
MCSI-STBY-F: CON1.30(PWDN_F) D28.4(IN3) D28.7(OUT3) U64.28(PE6/CLK-FANOUT1/HDMI-CEC/I2S3-DIN0/I2S3-DOUT1/LPC-SERIRQ/NCSI0-D2/UART6-DTR/PE-EINT6)
MCSI-STBY-R: CON1.33(PWDN_B) D32.5(IN4) D32.6(OUT4) U64.30(PE8/CLK-FANOUT3/HDMI-SDA/I2S3-LRCK/LPC-LAD2/NCSI0-D4/TWI11-SDA/PE-EINT8)
MCSIA-CKN: CON1.14(MCN_B) D27.1(IN1) D27.10(OUT1) U64.18(PK4/MCSIA-CKN/PCIE-WAKEN/I2S4-DOUT0/I2S4-DIN1/SPI3-CS0/NCSI1-D15/JTAG-MAS-MS/PK-EINT4)
MCSIA-CKP: CON1.15(MCP_B) D27.2(IN2) D27.9(OUT2) U64.19(PK5/MCSIA-CKP/PCIE-CLKREQN/PWM1-8/PWM1-9/SPI3-CLK/NCSI1-D14/JTAG-MAS-CK/PK-EINT5)
MCSIA-D0N: CON1.11(MDN0_B) D30.4(IN3) D30.7(OUT3) U64.16(PK0/MCSIA-D0N/UART6-DCD/I2S4-BCLK/HDMI-CEC/TWI1-SDA/NCSI1-HSYNC/SGPIO-SLOAD/PK-EINT0)
MCSIA-D0P: CON1.12(MDP0_B) D30.5(IN4) D30.6(OUT4) U64.17(PK1/MCSIA-D0P/UART6-DSR/I2S4-MCLK/HDMI-SCL/TWI1-SCK/NCSI1-VSYNC/SGPIO-SCLK/PK-EINT1)
MCSIA-D1N: CON1.8(MDN1_B) D30.1(IN1) D30.10(OUT1) U64.14(PK2/MCSIA-D1N/UART6-DTR/I2S4-LRCK/HDMI-SDA/TWI5-SDA/NCSI1-PCLK/SGPIO-SDATAIN/PK-EINT2)
MCSIA-D1P: CON1.9(MDP1_B) D30.2(IN2) D30.9(OUT2) U64.15(PK3/MCSIA-D1P/UART6-RI/I2S4-DIN0/I2S4-DOUT1/TWI5-SCK/NCSI1-MCLK/SGPIO-SDATAOUT/PK-EINT3)
MCSIA-D2N: CON1.5(MDN2_B) D26.4(IN3) D26.7(OUT3) U64.12(PK6/MCSIA-D2N/TWI2-SCK/UART4-TX/UART2-RTS/SPI3-MOSI/NCSI1-D13/JTAG-MAS-DO/PK-EINT6)
MCSIA-D2P: CON1.6(MDP2_B) D26.5(IN4) D26.6(OUT4) U64.13(PK7/MCSIA-D2P/TWI2-SDA/UART4-RX/UART2-CTS/SPI3-MISO/NCSI1-D12/JTAG-MAS-DI/PK-EINT7)
MCSIA-D3N: CON1.2(MDN3_B) D26.1(IN1) D26.10(OUT1) U64.10(PK8/MCSIA-D3N/MCSI0-MCLK/UART4-RTS/UART2-TX/SPI3-CS1/NCSI1-D11/JTAG-MAS-NTRST/PK-EINT8)
MCSIA-D3P: CON1.3(MDP3_B) D26.2(IN2) D26.9(OUT2) U64.11(PK9/MCSIA-D3P/MCSI2-MCLK/UART4-CTS/UART2-RX/NCSI1-D10/JTAG-MAS-SRST/PK-EINT9)
MCSIC-CKN: CON1.23(MCN_F) D31.4(IN3) D31.7(OUT3) U64.24(PK24/MCSIC-CKN/MCSI0-MCLK/PWM0-6/TWI12-SCK/TWI10-SDA/PK-EINT24)
MCSIC-CKP: CON1.24(MCP_F) D31.5(IN4) D31.6(OUT4) U64.25(PK25/MCSIC-CKP/MCSI1-MCLK/PWM0-7/TWI12-SDA/TWI10-SCK/PK-EINT25)
MCSIC-D0N: CON1.20(MDN0_F) D31.1(IN1) D31.10(OUT1) U64.22(PK20/MCSIC-D0N/TWI2-SCK/UART3-TX/PWM0-1/NCSI1-PCLK/UART1-RTS/PK-EINT20)
MCSIC-D0P: CON1.21(MDP0_F) D31.2(IN2) D31.9(OUT2) U64.23(PK21/MCSIC-D0P/TWI2-SDA/UART3-RX/PWM0-2/NCSI1-MCLK/UART1-CTS/PK-EINT21)
MCSIC-D1N: CON1.17(MDN1_F) D27.4(IN3) D27.7(OUT3) U64.20(PK22/MCSIC-D1N/TWI3-SCK/UART3-RTS/PWM1-6/NCSI1-HSYNC/UART1-TX/PK-EINT22)
MCSIC-D1P: CON1.18(MDP1_F) D27.5(IN4) D27.6(OUT4) U64.21(PK23/MCSIC-D1P/TWI3-SDA/UART3-CTS/PWM1-7/NCSI1-VSYNC/UART1-RX/PK-EINT23)
MDI0+: J5.2(TD0+) U15.1(MDI[0]+)
MDI0-: J5.3(TD0-) U15.2(MDI[0]-)
MDI1+: J5.4(TD1+) U15.4(MDI[1]+)
MDI1-: J5.7(TD1-) U15.5(MDI[1]-)
MDI2+: J5.5(TD2+) U15.6(MDI[2]+)
MDI2-: J5.6(TD2-) U15.7(MDI[2]-)
MDI3+: J5.8(TD3+) U15.9(MDI[3]+)
MDI3-: J5.9(TD3-) U15.10(MDI[3]-)
MIC1N-MIC: DA2.2(CATHODE) MIC1.2(-) RA101.1
MIC1P-MIC: DA1.2(CATHODE) MIC1.1(+) RA100.1
MIC2N/MIC3N: RA80.2 UA1.39(MIC2N/MIC3N)
MIC2P/MIC3P: RA79.2 UA1.37(MIC2P/MIC3P)
MICIN1N: CA9.1 UA1.1(MIC1N)
MICIN1P: CA6.1 UA1.40(MIC1P)
MICIN4N: C182.1 UA1.4(LINEINL/MIC4N<MUX_MIC2N>)
MICIN4P: C181.1 UA1.3(LINEINR/MIC4P<MUX_MIC2P>)
PA-SHDN-PE15: R179.2 U6.1(CTRL) U64.133(PE15/SPI3-CS1/PWM1-9/IR-RX/TWI9-SDA/PE-EINT15)
PA-VDD: C70.1 C197.1 FB1.1 U6.6(VDD)
PHYRSTB: CE19.2 RE18.2 U15.12(PHYRSTB) U64.99(PH16/UART5-CTS/IR-TX/PH-EINT16)
PM5-BEEP: R51.1 U64.169(PM5/S-UART0-RX/S-TWI2-SDA/S-TWI1-SDA/S-UART1-RX/S-PWM0-1/S-IR-RX/PM-EINT5)
PWRON: C3.1 D4.2(CATHODE) K2.2 U64.168(PWRON)
REGOUT: L3.1 U15.30(REG_OUT)
RGMII0-CLK-25M: R109.1 U64.82(PH15/UART5-RTS/LEDC/DSI-TRIG-LCD-TE1/RGMII0-EPHY-25/50M/PH-EINT15)
RGMII0-CLKIN-125M: RE15.1 U64.83(PH3/TWI1-SDA/I2S2-BCLK/RGMII0-CLKIN/RMII0-RXER/SPI1-MISO/PH-EINT3)
RGMII0-MDC: U15.13(MDC) U64.98(PH8/DMIC-CLK/SPI2-CLK/RGMII0-MDC/PH-EINT8)
RGMII0-MDIO: RE21.2 U15.14(MDIO) U64.97(PH9/DMIC-DATA0/SPI2-CS0/RGMII0-MDIO/PH-EINT9)
RGMII0-RXCK: RE9.1 U64.84(PH12/DMIC-DATA3/SPI2-CS1/RGMII0-RXCK/RMII0-NULL/PH-EINT12)
RGMII0-RXCTL: RE14.1 U64.85(PH2/TWI1-SCK/I2S2-MCLK/RGMII0-RXCTL/RMII0-CRS-DV/SPI1-CS1/PH-EINT2)
RGMII0-RXD0: RE40.1 U15.25(RXD0/RXDLY) U64.86(PH1/TWI0-SDA/I2S2-DOUT3/I2S2-DIN3/RGMII0-RXD0/RMII0-RXD0/TWI3-SDA/SPI1-WP/PH-EINT1)
RGMII0-RXD1: RE38.1 U15.24(RXD1/TXDLY) U64.87(PH0/TWI0-SCK/I2S2-DOUT2/I2S2-DIN2/RGMII0-RXD1/RMII0-RXD1/TWI3-SCK/SPI1-HOLD/PH-EINT0)
RGMII0-RXD2: RE36.1 U15.23(RXD2/PLLOFF) U64.88(PH11/DMIC-DATA2/SPI2-MISO/RGMII0-RXD2/RMII0-NULL/PH-EINT11)
RGMII0-RXD3: RE25.1 U15.22(RXD3/PHYAD0) U64.89(PH10/DMIC-DATA1/SPI2-MOSI/RGMII0-RXD3/RMII0-NULL/PH-EINT10)
RGMII0-TXCK: RE7.1 U64.90(PH6/UART3-RTS/I2S2-DOUT1/I2S2-DIN0/RGMII0-TXCK/RMII0-TXCK/SPI1-CLK/PH-EINT6)
RGMII0-TXCTL: RE5.1 U64.91(PH7/UART3-CTS/SPI2-CS2/DSI-TRIG-LCD-TE1/RGMII0-TXCTL/RMII0-TXEN/PH-EINT7)
RGMII0-TXD0: U15.18(TXD0) U64.92(PH5/UART3-RX/I2S2-DIN1/I2S2-DOUT0/RGMII0-TXD0/RMII0-TXD0/SPI1-MOSI/PH-EINT5)
RGMII0-TXD1: U15.17(TXD1) U64.93(PH4/UART3-TX/SPI2-CS3/I2S2-LRCK/RGMII0-TXD1/RMII0-TXD1/SPI1-CS0/PH-EINT4)
RGMII0-TXD2: U15.16(TXD2) U64.94(PH14/UART5-RX/RGMII0-TXD2/RMII0-NULL/TWI7-SCK/PH-EINT14)
RGMII0-TXD3: U15.15(TXD3) U64.96(PH13/UART5-TX/RGMII0-TXD3/RMII0-NULL/TWI7-SDA/PH-EINT13)
RSET: RE22.2 U15.39(RSET)
RTC-IN: D174.2(CATHODE) J14.2 U64.166(BKUPBAT)
RX-1N: D13.5(IO4) D13.6(NC) J16.B10(RX1-) LU3.4 RU119.1
RX-1P: D13.4(IO3) D13.7(NC) J16.B11(RX1+) LU3.3 RU116.1
RX-2N: D12.1(IO1) D12.10(NC) J16.A10(RX2-) LU1.3 RU109.1
RX-2P: D12.2(IO2) D12.9(NC) J16.A11(RX2+) LU1.4 RU108.1
RXC/PHYAD1: RE9.2 RE23.2 U15.27(RXC/PHYAD1)
RXCTL/PHYAD2: RE14.2 RE34.2 U15.26(RXCTL/PHYAD2)
S-TWI0-CTP0-SCK: D47.2(IN2) D47.9(OUT2) J3.2 J10.6 R214.1 U64.178(PL8/S-TWI1-SCK/S-UART1-TX/S-TWI0-SCK/S-TWI2-SCK/S-PWM0-6/PL-EINT8)
S-TWI0-CTP0-SDA: D47.1(IN1) D47.10(OUT1) J3.1 J10.5 R7.1 U64.179(PL9/S-TWI1-SDA/S-UART1-RX/S-TWI0-SDA/S-TWI2-SDA/S-PWM0-7/PL-EINT9)
SBU1-DC: RU23.1 U64.175(PL5/S-JTAG-CK/S-TWI2-SDA/S-SPI0-CLK/S-PWM0-3/PL-EINT5)
SBU2-DC: RU24.1 U64.176(PL6/S-JTAG-DO/S-UART0-TX/S-SPI0-MOSI/S-IR-RX/S-PWM0-4/PL-EINT6)
SDC0-CLK: D49.1(IN1) D49.10(OUT1) J4.5(CLK) U64.74(PF2/SDC0-CLK/UART0-TX/TRACE-CLK/PF-EINT2)
SDC0-CMD: D126.2(CATHODE) J4.3(CMD) R11.2 U64.75(PF1/SDC0-CMD/JTAG-DO/TRACE-DATA2/PF-EINT1)
SDC0-D0: D49.2(IN2) D49.9(OUT2) J4.7(DAT0) U64.73(PF3/SDC0-D0/JTAG-DI/TRACE-DATA0/UART5-CTS/TWI2-SDA/PF-EINT3)
SDC0-D1: D49.4(IN3) D49.7(OUT3) J4.8(DAT1) U64.72(PF0/SDC0-D1/JTAG-MS/TRACE-DATA3/UART5-RTS/TWI2-SCK/PF-EINT0)
SDC0-D2: D128.2(CATHODE) J4.1(DAT2) U64.77(PF5/SDC0-D2/JTAG-CK/TRACE-DATA1/UART5-TX/PF-EINT5)
SDC0-D3: D127.2(CATHODE) J4.2(DAT3) U64.76(PF4/SDC0-D3/UART0-RX/UART5-RX/PF-EINT4)
SDC0-DET: D49.5(IN4) D49.6(OUT4) R294.1 U64.71(PF6/PF-EINT6)
SPI0-CLK: D91.1(IN1) D91.10(OUT1) J30.2 U64.150(PC12/NAND-DQS/SPI0-CLK/SPIF0-CLK/PC-EINT12)
SPI0-CS0: D91.5(IN4) D91.6(OUT4) J30.5 U64.147(PC3/NAND-CE1/SPI0-CS0/SPIF0-CS0/PC-EINT3)
SPI0-CS1: D88.1(ANODE) J30.1 U64.146(PC7/NAND-RB1/SPI0-CS1/SPIF0-DQS/PC-EINT7)
SPI0-MISO: D91.4(IN3) D91.7(OUT3) J30.4 U64.148(PC4/NAND-CE0/SPI0-MISO/SPIF0-MISO/PC-EINT4)
SPI0-MOSI: D91.2(IN2) D91.9(OUT2) J30.3 U64.149(PC2/NAND-CLE/SPI0-MOSI/SPIF0-MOSI/PC-EINT2)
SPKR+: CA85.1 D118.2(CATHODE) J37.1 U6.8(VOP)
SPKR-: CA88.1 D20.2(CATHODE) J37.2 R181.2 U6.5(VON)
SPOLN: R192.1 UA1.12(SPOLN)
SPOLP: R193.1 UA1.11(SPOLP)
SPORN: R194.1 UA1.10(SPORN)
SPORP: R191.1 UA1.9(SPORP)
TRM-CTR: C81.2 J5.1(GND)
TWI8-SCK: RA27.1 U64.115(PB9/UART0-TX/I2S0-DIN2/I2S0-DOUT2/PWM1-1/WATCHDOG-SIG/LCD0-D16/TWI8-SCK/TWI0-SCK/PB-EINT9) UA1.32(SCK)
TWI8-SDA: RA28.1 U64.116(PB10/UART0-RX/I2S0-DIN3/I2S0-DOUT3/PWM1-2/PLL-LOCK-DBG/LCD0-D17/TWI8-SDA/TWI0-SDA/PB-EINT10) UA1.31(SDA)
TX-1N: D13.2(IO2) D13.9(NC) J16.A3(TX1-) LU5.4 RU112.1
TX-1P: D13.1(IO1) D13.10(NC) J16.A2(TX1+) LU5.3 RU111.1
TX-2N: D12.4(IO3) D12.7(NC) J16.B3(TX2-) LU4.3 RU114.1
TX-2P: D12.5(IO4) D12.6(NC) J16.B2(TX2+) LU4.4 RU113.1
TXC: RE7.2 U15.20(TXC)
TXCTL: RE5.2 U15.19(TXCTL)
TYPEC-RX1N: LU3.1 R76.2 RU119.2
TYPEC-RX1P: LU3.2 R77.2 RU116.2
TYPEC-RX2N: LU1.2 R65.2 RU109.2
TYPEC-RX2P: LU1.1 R69.2 RU108.2
TYPEC-TX1N: C139.2 LU5.1 RU112.2
TYPEC-TX1P: C140.2 LU5.2 RU111.2
TYPEC-TX2N: C141.2 LU4.2 RU114.2
TYPEC-TX2P: C142.2 LU4.1 RU113.2
U3-TXN: C213.2 D74.1(ANODE) USB4.17(TX2-)
U3-TXP: C214.2 D75.1(ANODE) USB4.18(TX2+)
UART0-RX: D173.1(ANODE) R291.1 U64.107(PB1/UART2-RX/UART0-RX/SPI2-CLK/LCD0-D1/JTAG-CK/PB-EINT1)
UART0-TX: U11.9(RXD) U64.106(PB0/UART2-TX/UART0-TX/SPI2-CS0/DSI-TRIG-LCD-TE1/LCD0-D0/JTAG-MS/PB-EINT0)
UART2-RX: D54.1(ANODE) R44.1 U64.105(PJ27/PWM1-9/UART4-CTS/UART2-RX/DSI-TRIG-LCD-TE1/TWI5-SDA/SPI3-CS0/LCD0-D17/PJ-EINT27)
UART2-TX: R47.2 U4.4(DI) U64.104(PJ26/PWM1-8/UART4-RTS/UART2-TX/TWI5-SCK/SPI3-MISO/LCD0-D16/PJ-EINT26)
UART3-RX: D58.2(IN2) D58.9(OUT2) J22.3 U64.101(PJ23/PWM1-5/UART3-RX/UART2-CTS/TWI7-SDA/TWI3-SDA/TWI11-SDA/LCD0-D9/PJ-EINT23)
UART3-TX: D58.1(IN1) D58.10(OUT1) J22.2 U64.100(PJ22/PWM1-4/UART3-TX/UART2-RTS/TWI7-SCK/TWI3-SCK/TWI11-SCK/LCD0-D8/PJ-EINT22)
UART4-RX: D58.5(IN4) D58.6(OUT4) J38.3 U64.103(PJ25/PWM1-7/UART4-RX/TWI4-SDA/SPI3-MOSI/PJ-EINT25)
UART4-TX: D58.4(IN3) D58.7(OUT3) J38.2 U64.102(PJ24/PWM1-6/UART4-TX/TWI4-SCK/SPI3-CLK/PJ-EINT24)
UPUSB-DM: LU2.3 RU22.1 U10.5(UDM)
UPUSB-DP: LU2.4 RU19.1 U10.6(UDP)
USB0-DM: U14.7(C0-) U64.117(USB0-DM)
USB0-DM-L0-: D171.1(ANODE) U14.2(L0-) USB4.2(D1-)
USB0-DM-L1-: U10.1(DM2) U14.4(L1-)
USB0-DP: U14.8(C0+) U64.118(USB0-DP)
USB0-DP-L0+: D170.1(ANODE) U14.1(L0+) USB4.3(D1+)
USB0-DP-L1+: U10.2(DP2) U14.3(L1+)
USB0-SL-PL2: RU6.2 U14.9(SEL) U64.172(PL2/S-UART1-TX/S-UART0-TX/S-TWI1-SDA/S-PWM0-0/PL-EINT2)
USB1-DM: CON2.36(USB_DM) U64.119(USB1-DM)
USB1-DP: CON2.38(USB_DP) U64.120(USB1-DP)
USB2-DM: D71.1(ANODE) U64.123(USB2-DM) USB4.11(D2-)
USB2-DP: D70.1(ANODE) U64.124(USB2-DP) USB4.12(D2+)
USIM_CLK: CON2.12(USIM_CLK) D52.4(IN3) D52.7(OUT3) J8.3(CLK)
USIM_DATA: CON2.10(USIM_DATA) D52.2(IN2) D52.9(OUT2) J8.7(I/0)
USIM_RST: CON2.14(USIM_RESET) D52.5(IN4) D52.6(OUT4) J8.2(RST)
USIM_VCC: CON2.8(USIM_POWER) D52.1(IN1) D52.10(OUT1) J8.1(VCC)
VCOM: J39.1(VCOM) R199.2 R289.1
VDD-CORE/HP-DET: CA11.1 RA12.1 UA1.35(VDD-CORE/HP_DET)
VGH: C60.1 C233.1 D82.2(CATHODE) J39.38(VGH) R59.2 R60.2
VGL: C55.1 C58.1 D84.1(ANODE) J39.35(VGL) R61.2 R62.2
VRA1/MIC2P: CA2.1 UA1.14(VRA1/MIC2P<MUX_MIC4P>)
VRA2/MIC2N: CA4.2 RA6.2 UA1.13(VRA2/MIC2N<MUX_MIC4N>)
W_DISABLE_N: CON2.20(W_DISABLE_N) R100.1
XTAL-25MIN: CE18.2 U15.36(XTAL_IN) X1.3
XTAL-25MOUT: CE17.2 R109.2 U15.37(XTAL_OUT/EXT_CLK) X1.1
N39839: J4.9(CD#) R10.2 R294.2
N638326: J5.14(YELLOW+) R81.1
N638520: J5.11(GREEN+) R79.1
N5679088: C92.2 L1.1 U2.6(LX)
N5679096: C92.1 U2.1(BS)
N5679154: C93.2 R2.2 R159.1 U2.3(FB/OUT)
N5680029: F1.1 J1.1
N16925291: D46.1(ANODE) L4.2 U13.1(SW)
N17131711: D86.2 R28.1
N17174872: CON2.42(LED_WWAN_N) R101.1
N17174874: D53.2(CATHODE) R101.2
N17175777: Q3.3(COLLECTOR) R43.2 R45.1 U4.2(~{RE}) U4.3(DE)
N17175783: D54.2(CATHODE) U4.1(RO)
N17177143: C191.2 L2.1 U12.6(LX)
N17177153: C192.2 R173.2 R174.1 U12.3(FB/OUT)
N17255318: Q4.1(BASE) R51.2
N17255336: D93.1(ANODE) J7.2 Q4.3(COLLECTOR)
N17680063: L5.1 U28.3(SW)
N17680065: C7.2 R266.1 R267.2 U28.5(VFB)
N17819196: CA25.1 UA1.16(VEE) UA1.20(CPVEE)
N17819206: CA26.1 UA1.23(CPP)
N17819214: CA26.2 UA1.21(CPN)
N17819230: CA23.1 UA1.34(BYPASS/VDD-CORE)
N17819689: CA3.2 CA6.2 CA7.1 RA7.2 RA100.2
N17819691: CA7.2 CA9.2 CA12.1 RA11.2 RA101.2
N17819723: CA8.2 RA11.1 RA13.1
N17819725: CA8.1 RA5.1 RA7.1
N17838408: C181.2 R195.1
N17838410: C182.2 R196.1
N17838457: C88.1 D17.2(CATHODE) J36.3(L) R25.1 R157.2
N17838500: C89.1 D19.2(CATHODE) J36.4(R)
N17838683: D18.2(CATHODE) R20.2 R23.2 R157.1
N17845378: C111.2 R191.2 R193.2
N17845396: C72.2 R192.2 R194.2
N17845478: C111.1 U6.3(IN+)
N17845505: C72.1 R181.1 U6.4(IN-)
N17845570: C69.1 U6.2(BYPASS)
N17865326: Q3.1(BASE) R47.1
N17865327: C37.2 R43.1
N17874598: CA83.2 CA84.1 CA86.1 RA61.1 RA62.2
N17874616: CA86.2 CA87.1 CA89.1 RA63.2 RA65.2
N17874634: CA85.2 RA62.1
N17874636: CA88.2 RA63.1
N17914489: R38.2 R209.1 R210.1 U63.4(EN)
N17914651: C53.2 C57.1 D125.1(ANODE) L7.2 U63.1(SW)
N17914681: C53.1 D81.3
N17914691: C231.2 D83.1 R61.1
N17914697: R207.1 R208.1 U63.3(FB)
N17914762: C232.1 D81.2 R59.1
N17915278: J39.6(STBYB) R205.1 R206.2
N17963617: RU1.2 U3.3(ISET)
N17967381: C220.1 Q8.3(BASE) RU6.1 U14.10(VDD)
N17967469: U10.12(XIN) X3.1
N17967471: U10.11(XOUT) X3.3
N17967477: C173.1 U10.10(VDD18)
N17967572: D173.2(CATHODE) U11.8(TXD)
N18037529: C191.1 U12.1(BS)
N18037530: D3.2(CATHODE) R4.2
N18042692: C143.1 U64.136(DP-AUXP)
N18042694: C144.1 U64.135(DP-AUXN)
N18042720: C139.1 U64.138(TYPEC-TX1N/U3-TX0N/DP/EDP-TX0N)
N18042722: C140.1 U64.137(TYPEC-TX1P/U3-TX0P/DP/EDP-TX0P)
N18042768: R65.1 U64.142(TYPEC-RX2N/U3-RX0N/DP/EDP-TX2N)
N18042770: R69.1 U64.141(TYPEC-RX2P/U3-RX0P/DP/EDP-TX2P)
N18042772: R76.1 U64.140(TYPEC-RX1N/U3-RX0P/DP/EDP-TX1N)
N18042774: R77.1 U64.139(TYPEC-RX1P/U3-RX0N/DP/EDP-TX1P)
N18042804: C141.1 U64.144(TYPEC-TX2N/U3-TX0N/DP/EDP-TX3N)
N18042806: C142.1 U64.143(TYPEC-TX2P/U3-TX0P/DP/EDP-TX3P)
N18056847: C57.2 D83.3

Not connected (* = marked no-connect by the designer): CON2 1(N/C1)* 3(N/C2)* 5(N/C3)* 6(N/C4)* 7(N/C5)* 11(N/C6)* 13(N/C7)* 16(USIM_VPP)* 17(N/C8)* 19(N/C9)* 22(PERST_N)* 23(N/C10)* 25(N/C11)* 28(N/C12)* 30(N/C13)* 31(N/C14)* 32(N/C15)* 33(N/C16)* 44(N/C17)* 45(Reserved1)* 46(N/C18)* 47(Reserved2)* 48(N/C19)* 49(Reserved3)* 50(N/C20)* 51(Reserved4)* G1* G2*; FID1 1(TP)*; FID2 1(TP)*; FID3 1(TP)*; FID5 1(TP)*; H1 1(TP); H2 1(TP); H3 1(TP); H4 1(TP); H6 1(TP); H7 1(TP); J1 4 5 6* 7*; J2 1; J5 15(SHELL1)* 16(SHELL2)* 17(FIX1)* 18(FIX2)* 19(G+)* 20(G-)* 21(Y-)* 22(Y+)*; J8 4* 6(VPP)*; J16 5(Shield5)* 6(Shield6)*; J36 1(N); J39 4(NC) 23(NC) 24(NC) 26(NC) 27(DIMO) 36(NC) 37(NC); TP0 1(TP); TP3 1(TP); U10 3(DM1) 4(DP1) 13(DM4) 14(DP4); U11 4(RTS#) 5(CTS#) 6(TNOW); U15 34(LED2/CFG_LDO1); U17 14(RESERVED); U64 1(PK14/MCSIB-CKN/PCIE-PERSTN/PWM0-7/NCSI1-D5/PK-EINT14)* 2(PK15/MCSIB-CKP/PWM0-8/NCSI1-D4/PK-EINT15)* 3(PK16/MCSIB-D2N/TWI3-SCK/UART2-TX/PWM0-9/NCSI1-D3/PK-EINT16)* 4(PK17/MCSIB-D2P/TWI3-SDA/UART2-RX/PWM1-0/NCSI1-D2/PK-EINT17)* 5(PK18/MCSIB-D3N/MCSI1-MCLK/UART2-RTS/PWM1-1/NCSI1-D1/TWI9-SCK/PK-EINT18)* 130(PE13/SPI3-CLK/PCIE-PERSTN/UART1-RX/PE-EINT13)* 131(PE14/SPI3-MOSI/PWM1-8/PCIE-CLKREQN/IR-RX/TWI9-SCK/PE-EINT14)* 132(PE12/SPI3-CS0/I2S3-DOUT0/I2S3-DIN1/PCIE-WAKEN/UART1-TX/PE-EINT12)* 134(DP-HPD)* 151(PC15/NAND-DQ1/SDC2-D2/SDC3-D2/SPI0-WP/SPIF0-WP/PC-EINT15)* 152(PC16/NAND-DQ0/SDC2-D7/SDC3-D7/SPI0-HOLD/SPIF0-HOLD/PC-EINT16)* 153(PC13/NAND-DQ3/SDC2-D1/SDC3-D1/PC-EINT13)* 154(PC14/NAND-DQ2/SDC2-D6/SDC3-D6/PC-EINT14)* 159(PMU-IRQ)* 160(PMU-SCK)* 161(PMU-SDA)* 174(PL4/S-JTAG-MS/S-TWI2-SCK/S-SPI0-CS0/S-IR-RX/S-PWM0-2/PL-EINT4) 184(PK12/MCSIB-D1N/UART6-RTS/PWM0-5/NCSI1-D7/PK-EINT12)* 185(PK13/MCSIB-D1P/UART6-CTS/PWM0-6/NCSI1-D6/PK-EINT13)* 186(PK10/MCSIB-D0N/UART6-TX/PWM0-3/NCSI1-D9/PK-EINT10)* 187(PK11/MCSIB-D0P/UART6-RX/PWM0-4/NCSI1-D8/PK-EINT11)*; USB4 5(RX1-) 6(RX1+) 8(TX1-) 9(TX1+)

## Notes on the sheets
sheet 1
- 修改日志（Change Logs）
- V1.3
- 首次对外发布版本（First release）
sheet 2
- 1.if not used USB3.0&PCIE2.1 PCIE-REF-CLKP/N
  tie to GND,power&signal pin can floating
  2.if used USB3.0,PCIE-REF-CLKP/N tie to GND,PCIE-TEST tie to test port.
  3.if used PCIE2.1,PCIE-TEST tie to test port.
- 注意：
  专用接口-PMU-IRQ/PMU-SCK/PMU-SDA，禁止使用
  Note:
  Special interface - PMU-IRQ/PMU-SCK/PMU-SDA, do not use
- 3.3V  PB PH PJ PL
- 1.8V  PM PK PE PC
- 注意：
  核心板供电电流需要1.5A@5V以上。
  Note:
  The power supply current of the core board
  needs more than 1.5A@5V
- NOTE:Combo0 100nF Cap placement
  need to close SOC：
  C139/C140/C141/C142
- V1.8
sheet 3
- DCIN
- 9V<VIN<18V
- 4.5V<VIN<18V
sheet 4
- Camera
- 注意：
  MCSIA和 MCSIB、MCSIC 和 MCSID 才能组合成 4line 使用，MCSIA 和
  MCSIB 用作 4line 时，需使用 MCSIA
  的 CLK，MCSIB 的 CLK 可以悬空，也可以用作普通 IO，其中
  MCSIA0、MCSIA1、MCSIB0、MCSIB1
  依次对应 MCSI0/1/2/3；MCSIC 和 MCSID 用作 4line 时，需使用
  MCSIC 的 CLK，MCSID 的 CLK
  可以悬空，也可以用作普通 IO，其中
  MCSIC0、MCSIC1、MCSID0、MCSID1 依次对应 MCSI0/1/2/3
  Attention:
  MCSIA and MCSIB, MCSIC and MCSID can be combined to form 4line
  When MCSIA and MCSIB are used as 4Lines,
  use MCSIA
  The CLK of MCSIB can be suspended or used as normal
  IO, where MCSIA0, MCSIA1, MCSIB0, and MCSIB1 are displayed
  Corresponding to MCSI0/1/2/3;
  MCSIC and MCSID are used as 4lines
  ", the CLK of MCSIC and CLK of MCSID are required
  Can be suspended, can also be used as ordinary IO,where
  MCSIC0, MCSIC1, MCSID0, and MCSID1 correspond in sequence
  MCSI0/1/2/3
- 1.8V
sheet 5
- LCD
- MIPI/LVDS
- 9.43V
- 3.6V
- 9.43V
- LCD   select
- 此处上拉电平跟IO电平一致
  The pull-up level here is consistent with the IO level
sheet 6
- 4G
sheet 7
- ETH
- 20mil
- 20mil
- 20mil
- PHY RESET/INTB
- Close to PHY PIN11 and PIN40 for Analog Power
- Enable/Disable PLL @ ALDPS
- Pull-up to disable PLL @ ALDPS mode.
- Close to PHY PIN29 for Digital Power & SWR
- Close to  CORE
- RGMII TXC/RXC Delay Config.
- Pull-up for additional 2ns delay to TXC/RXC for data latching.
- PHY Address Config.
- Crystal Case
sheet 8
- HDMI
- Differential pairs
  Z0= 100 ohm
- Max 500mA
- Max 1mA
- 修复HCEC与HDMI-HCEC连接
  Fix HCEC connection error with HDMI-HCEC
- 注意，此处信号为TypeA排列，
  和TypeB,C座子信号排列不同
sheet 9
- 485
- UART3
- UART4
sheet 10
- TF
- RTC
- 内部有上拉，可以NC R10,R11
  There is an internal pull-up, and it can be NC R10, R11.
- SDIO2.0
- 此处上拉电平跟IO电平一致
  The pull-up level here is consistent with the IO level
- 此插座可扩展按键电路
  This socket can expand the key circuit.
sheet 11
- TYPEC
- TYPC-C CONNECTOR
- USB OTG
- 2500mA
- 10mA
- HUB1
- 注意：
  蓝色框内电路可以移除(方便调试用途)。
  J15的DM,DP分别连核心板上USB0-DM,UDB0-DP。
  UART0需要引出来用于调试。
  Note:
  The circuit in the blue box can be removed (for easy debugging purposes).
  The DM and DP of the J15 are connected to the USB0-DM and UDB0-DP on the core board respectively.
  UART0 needs to be extracted for debugging
- USB2.0/USB3.0
- 100 mil
sheet 12
- SPI
- BEEP
sheet 13
- ECM MIC
- AC101/AC101B
- OPTION1
- OPTION2
- R1/R2/R3/R4 Value according to Audio test results
- C1
- AC101
- AC101B
- option 1
- USE
- NC
- R4
- For AC101, paste resistor 0R
  For AC101B, paste capacitor 4.7uF
- option 2
- NC
- USE
- MIC1
- C1
- 10uF
- 2.2uF
- R1
- 0R
- 4.7uF
- C2
- C3
- 1uF
- 2.2uF
- 0.47uF
- 1uF
- R3
- R1
- C4
- 1uF
- 0.1uF
- option 3
- AC107 NC
- AC107 USE
- C1
- C3
- RA1
- NC
- NC
- 0R
- RA2
- NC
- NC
- 0R
- D1
- RA3
- 0R
- 0R
- NC
- C2
- RA4
- RA5
- 0R
- NC
- 0R
- 0R
- NC
- NC
- C2
- R1
- RA6
- NC
- 0R
- NC
- R2
- RA7
- NC
- 0R
- NC
- RA8
- NC
- 0R
- NC
- NOTE:
- NC AC107,use AC101B only support single ECM MIC.
  NC AC107,use AC101 not support ECM MIC.
- Close to MIC
- R1/R2/R3/R4 Value according to Audio test results
- Close to Codec
- 3.3V 50mA
- C3
- Component
- Diferential
- single-ended
- 为了与AC101兼容省电阻，默认选择上拉；
  DEVID有两组I2C地址，为了一组I2C控制两颗AC101B使用；
- R1 R2 C1
  C3 D1
- USE
- NC
- C4
- C2
- 33PF
- 0R
- R3
- 2.2K
- 1K
- SPEAKER
- 1.8V 50mA
- RA3
- RA4
- AEC
- 回声消除
- R4
- C4
- R5
- C5
- The value of R5 and R4 are
  seted by the amplitude of AEC
- Note:
  Vaec=Vspk*R4/(R4+R5)
  -3dB Cut-off Frequency:
  f=1/2π(R5//R4)C4
- HEADPHONE
- R5
- C5
- R4
- C5 are changed to 1uF
  for lowpower application.
- C4
- HP_JACK
- SPEAKEFR
- PJ-327F  PCB封装参考此图
  PJ-327F  PCB package refer to this figure
- L
- R
- GND
- MIC
- CTIA：RA1 RA2=0R,RN1 RN2=NC Europe
  OMTP：RN1 RN2=0R,RA1 RA2=NC China
- CTIA
- TYPEC AUDIO
- Close to Codec
- connect to GND and
  close to HP jack
- Note:
- TYPE-C audio also need those circuit.
- Note:
  HPOUTFB must connect to GND，whether HPOUTL/HPOUTR is used.
